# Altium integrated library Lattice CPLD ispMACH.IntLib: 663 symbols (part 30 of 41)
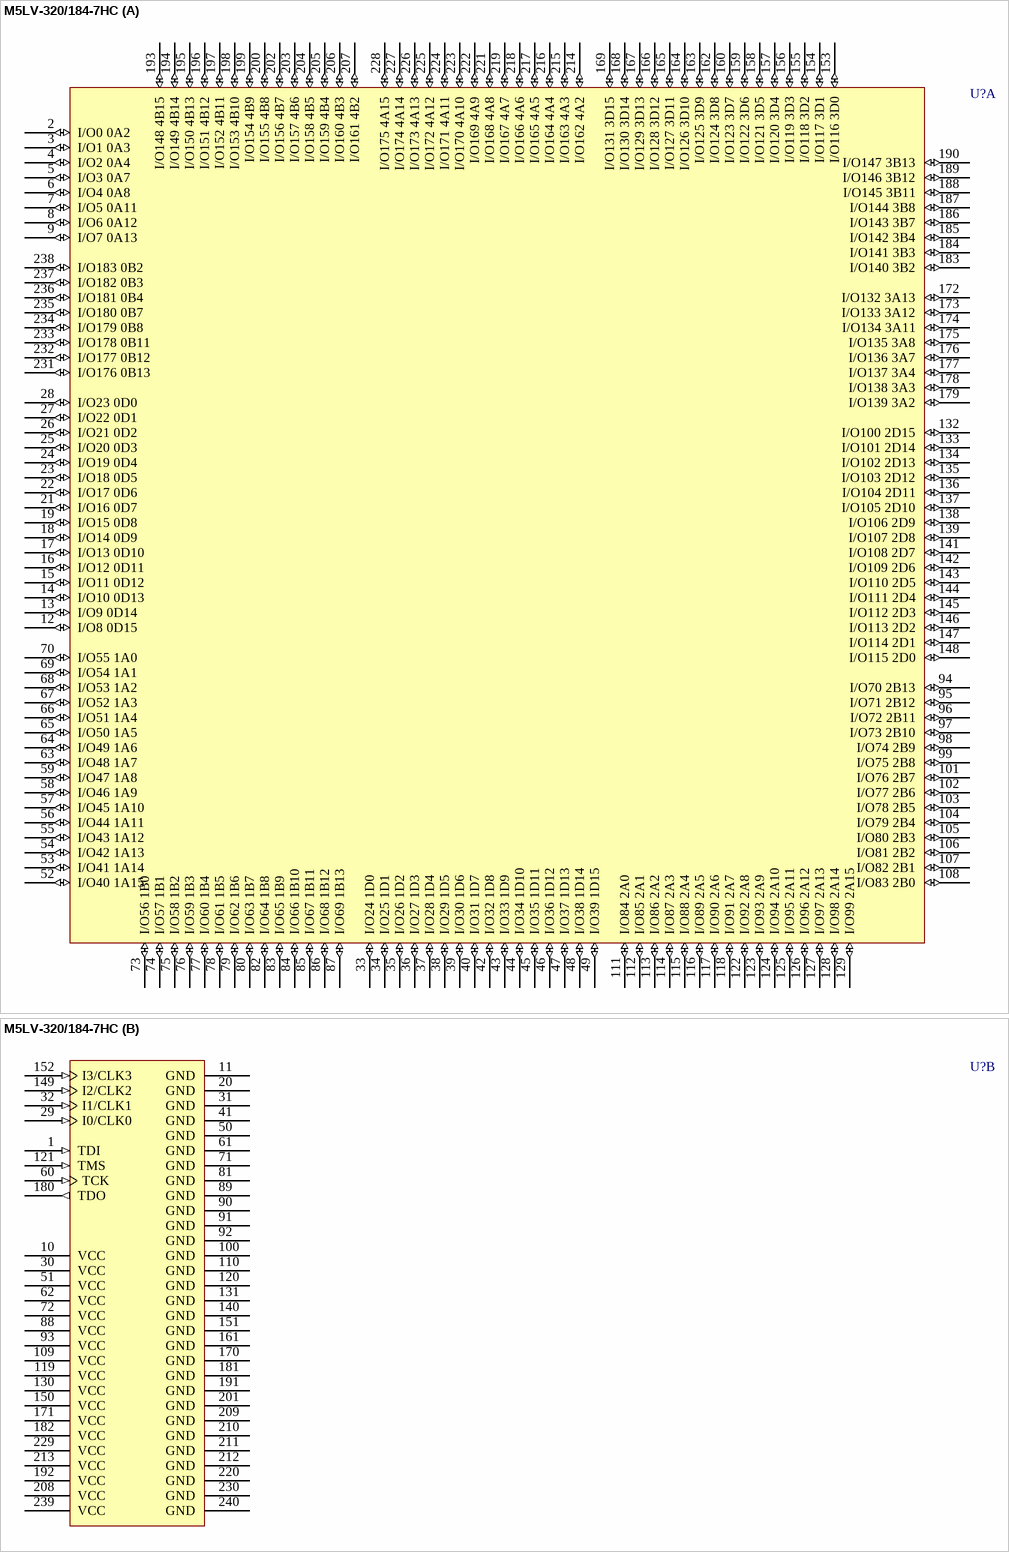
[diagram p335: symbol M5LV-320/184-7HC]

## M5LV-320/184-7HC
designator U?
High-Density and High-I/O Complex PLD
footprint PQFP240_N (Shrink QFP, 240-Leads, Body 32x32mm, Pitch 0.5mm, IPC Medium Density)
footprint PQFP240_L (Shrink QFP, 240-Leads, Body 32x32mm, Pitch 0.5mm, IPC High Density)
footprint PQFP240_M (Shrink QFP, 240-Leads, Body 32x32mm, Pitch 0.5mm, IPC Low Density)
3D model M5LV-PQFP240 (240-Pin Shrink Quad Flat Pack 0.5 mm Pitch)
part A pins: 2 I/O0 0A2 (io), 3 I/O1 0A3 (io), 4 I/O2 0A4 (io), 5 I/O3 0A7 (io), 6 I/O4 0A8 (io), 7 I/O5 0A11 (io), 8 I/O6 0A12 (io), 9 I/O7 0A13 (io), 12 I/O8 0D15 (io), 13 I/O9 0D14 (io), 14 I/O10 0D13 (io), 15 I/O11 0D12 (io), 16 I/O12 0D11 (io), 17 I/O13 0D10 (io), 18 I/O14 0D9 (io), 19 I/O15 0D8 (io), 21 I/O16 0D7 (io), 22 I/O17 0D6 (io), 23 I/O18 0D5 (io), 24 I/O19 0D4 (io), 25 I/O20 0D3 (io), 26 I/O21 0D2 (io), 27 I/O22 0D1 (io), 28 I/O23 0D0 (io), 33 I/O24 1D0 (io), 34 I/O25 1D1 (io), 35 I/O26 1D2 (io), 36 I/O27 1D3 (io), 37 I/O28 1D4 (io), 38 I/O29 1D5 (io), 39 I/O30 1D6 (io), 40 I/O31 1D7 (io), 42 I/O32 1D8 (io), 43 I/O33 1D9 (io), 44 I/O34 1D10 (io), 45 I/O35 1D11 (io), 46 I/O36 1D12 (io), 47 I/O37 1D13 (io), 48 I/O38 1D14 (io), 49 I/O39 1D15 (io), 52 I/O40 1A15 (io), 53 I/O41 1A14 (io), 54 I/O42 1A13 (io), 55 I/O43 1A12 (io), 56 I/O44 1A11 (io), 57 I/O45 1A10 (io), 58 I/O46 1A9 (io), 59 I/O47 1A8 (io), 63 I/O48 1A7 (io), 64 I/O49 1A6 (io), 65 I/O50 1A5 (io), 66 I/O51 1A4 (io), 67 I/O52 1A3 (io), 68 I/O53 1A2 (io), 69 I/O54 1A1 (io), 70 I/O55 1A0 (io), 73 I/O56 1B0 (io), 74 I/O57 1B1 (io), 75 I/O58 1B2 (io), 76 I/O59 1B3 (io), 77 I/O60 1B4 (io), 78 I/O61 1B5 (io), 79 I/O62 1B6 (io), 80 I/O63 1B7 (io), 82 I/O64 1B8 (io), 83 I/O65 1B9 (io), 84 I/O66 1B10 (io), 85 I/O67 1B11 (io), 86 I/O68 1B12 (io), 87 I/O69 1B13 (io), 94 I/O70 2B13 (io), 95 I/O71 2B12 (io), 96 I/O72 2B11 (io), 97 I/O73 2B10 (io), 98 I/O74 2B9 (io), 99 I/O75 2B8 (io), 101 I/O76 2B7 (io), 102 I/O77 2B6 (io), 103 I/O78 2B5 (io), 104 I/O79 2B4 (io), 105 I/O80 2B3 (io), 106 I/O81 2B2 (io), 107 I/O82 2B1 (io), 108 I/O83 2B0 (io), 111 I/O84 2A0 (io), 112 I/O85 2A1 (io), 113 I/O86 2A2 (io), 114 I/O87 2A3 (io), 115 I/O88 2A4 (io), 116 I/O89 2A5 (io), 117 I/O90 2A6 (io), 118 I/O91 2A7 (io), 122 I/O92 2A8 (io), 123 I/O93 2A9 (io), 124 I/O94 2A10 (io), 125 I/O95 2A11 (io), 126 I/O96 2A12 (io), 127 I/O97 2A13 (io), 128 I/O98 2A14 (io), 129 I/O99 2A15 (io), 132 I/O100 2D15 (io), 133 I/O101 2D14 (io), 134 I/O102 2D13 (io), 135 I/O103 2D12 (io), 136 I/O104 2D11 (io), 137 I/O105 2D10 (io), 138 I/O106 2D9 (io), 139 I/O107 2D8 (io), 141 I/O108 2D7 (io), 142 I/O109 2D6 (io), 143 I/O110 2D5 (io), 144 I/O111 2D4 (io), 145 I/O112 2D3 (io), 146 I/O113 2D2 (io), 147 I/O114 2D1 (io), 148 I/O115 2D0 (io), 153 I/O116 3D0 (io), 154 I/O117 3D1 (io), 155 I/O118 3D2 (io), 156 I/O119 3D3 (io), 157 I/O120 3D4 (io), 158 I/O121 3D5 (io), 159 I/O122 3D6 (io), 160 I/O123 3D7 (io), 162 I/O124 3D8 (io), 163 I/O125 3D9 (io), 164 I/O126 3D10 (io), 165 I/O127 3D11 (io), 166 I/O128 3D12 (io), 167 I/O129 3D13 (io), 168 I/O130 3D14 (io), 169 I/O131 3D15 (io), 172 I/O132 3A13 (io), 173 I/O133 3A12 (io), 174 I/O134 3A11 (io), 175 I/O135 3A8 (io), 176 I/O136 3A7 (io), 177 I/O137 3A4 (io), 178 I/O138 3A3 (io), 179 I/O139 3A2 (io), 183 I/O140 3B2 (io), 184 I/O141 3B3 (io), 185 I/O142 3B4 (io), 186 I/O143 3B7 (io), 187 I/O144 3B8 (io), 188 I/O145 3B11 (io), 189 I/O146 3B12 (io), 190 I/O147 3B13 (io), 193 I/O148 4B15 (io), 194 I/O149 4B14 (io), 195 I/O150 4B13 (io), 196 I/O151 4B12 (io), 197 I/O152 4B11 (io), 198 I/O153 4B10 (io), 199 I/O154 4B9 (io), 200 I/O155 4B8 (io), 202 I/O156 4B7 (io), 203 I/O157 4B6 (io), 204 I/O158 4B5 (io), 205 I/O159 4B4 (io), 206 I/O160 4B3 (io), 207 I/O161 4B2 (io), 214 I/O162 4A2 (io), 215 I/O163 4A3 (io), 216 I/O164 4A4 (io), 217 I/O165 4A5 (io), 218 I/O166 4A6 (io), 219 I/O167 4A7 (io), 221 I/O168 4A8 (io), 222 I/O169 4A9 (io), 223 I/O170 4A10 (io), 224 I/O171 4A11 (io), 225 I/O172 4A12 (io), 226 I/O173 4A13 (io), 227 I/O174 4A14 (io), 228 I/O175 4A15 (io), 231 I/O176 0B13 (io), 232 I/O177 0B12 (io), 233 I/O178 0B11 (io), 234 I/O179 0B8 (io), 235 I/O180 0B7 (io), 236 I/O181 0B4 (io), 237 I/O182 0B3 (io), 238 I/O183 0B2 (io)
part B pins: 1 TDI (in), 10 VCC (power), 11 GND (power), 20 GND (power), 29 I0/CLK0 (in), 30 VCC (power), 31 GND (power), 32 I1/CLK1 (in), 41 GND (power), 50 GND (power), 51 VCC (power), 60 TCK (in), 61 GND (power), 62 VCC (power), 71 GND (power), 72 VCC (power), 81 GND (power), 88 VCC (power), 89 GND (power), 90 GND (power), 91 GND (power), 92 GND (power), 93 VCC (power), 100 GND (power), 109 VCC (power), 110 GND (power), 119 VCC (power), 120 GND (power), 121 TMS (in), 130 VCC (power), 131 GND (power), 140 GND (power), 149 I2/CLK2 (in), 150 VCC (power), 151 GND (power), 152 I3/CLK3 (in), 161 GND (power), 170 GND (power), 171 VCC (power), 180 TDO (out), 181 GND (power), 182 VCC (power), 191 GND (power), 192 VCC (power), 201 GND (power), 208 VCC (power), 209 GND (power), 210 GND (power), 211 GND (power), 212 GND (power), 213 VCC (power), 220 GND (power), 229 VCC (power), 230 GND (power), 239 VCC (power), 240 GND (power)

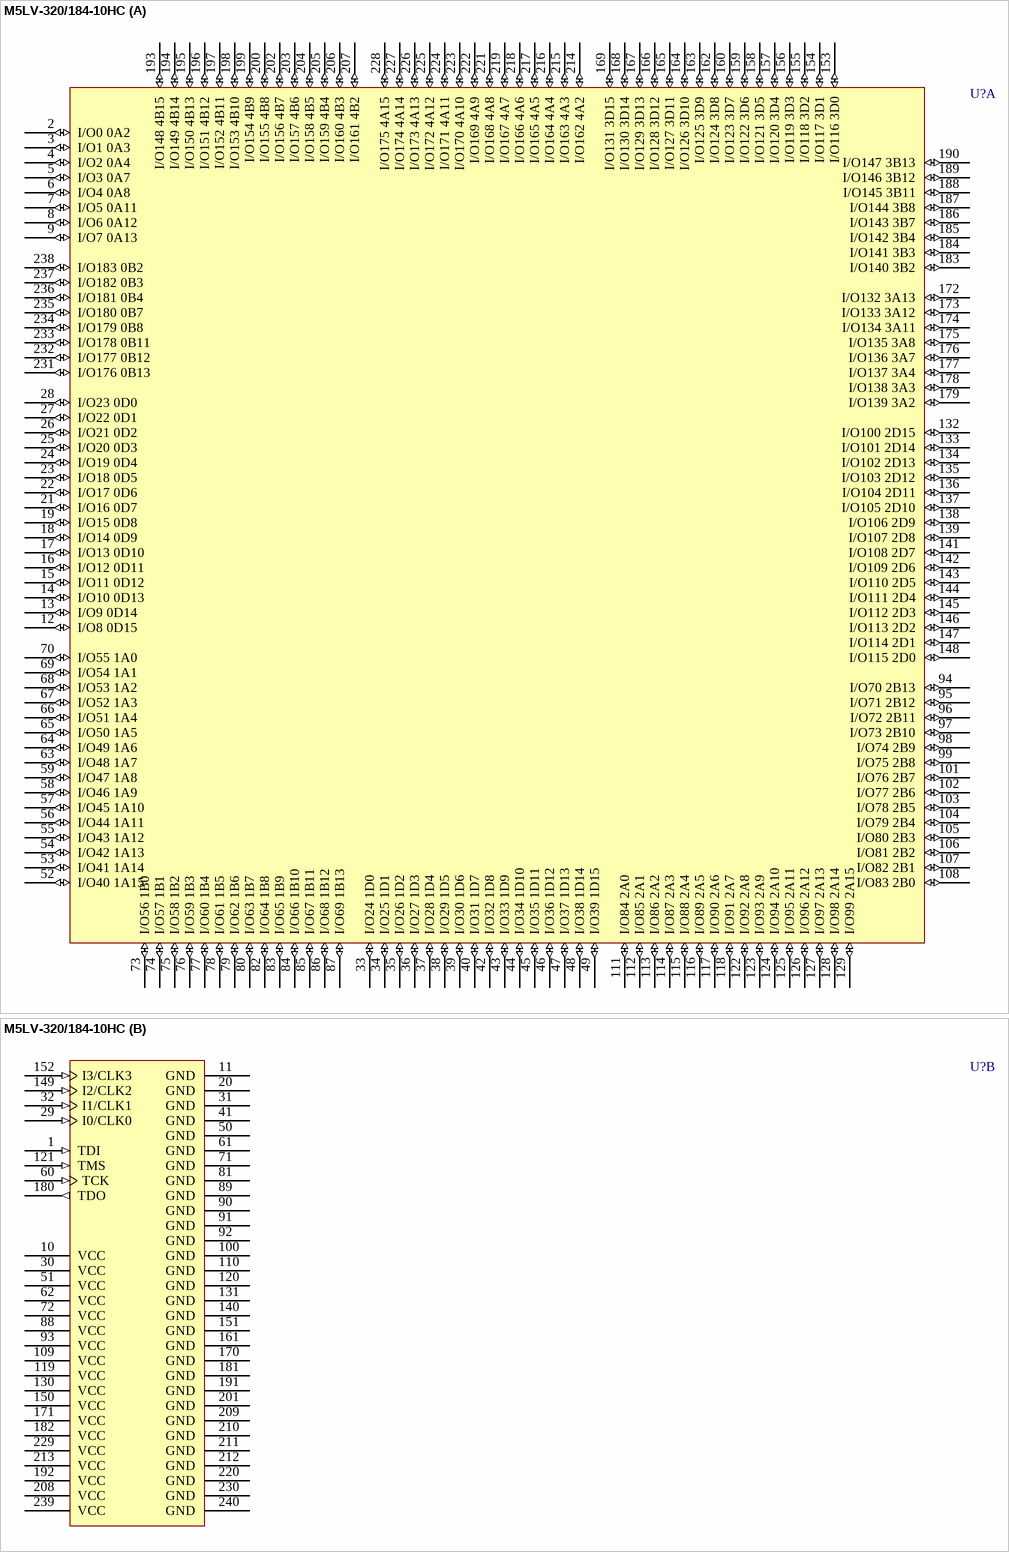
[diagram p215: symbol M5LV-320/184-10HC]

## M5LV-320/184-10HC
designator U?
High-Density and High-I/O Complex PLD
footprint PQFP240_N (Shrink QFP, 240-Leads, Body 32x32mm, Pitch 0.5mm, IPC Medium Density)
footprint PQFP240_L (Shrink QFP, 240-Leads, Body 32x32mm, Pitch 0.5mm, IPC High Density)
footprint PQFP240_M (Shrink QFP, 240-Leads, Body 32x32mm, Pitch 0.5mm, IPC Low Density)
3D model M5LV-PQFP240 (240-Pin Shrink Quad Flat Pack 0.5 mm Pitch)
part A pins: 2 I/O0 0A2 (io), 3 I/O1 0A3 (io), 4 I/O2 0A4 (io), 5 I/O3 0A7 (io), 6 I/O4 0A8 (io), 7 I/O5 0A11 (io), 8 I/O6 0A12 (io), 9 I/O7 0A13 (io), 12 I/O8 0D15 (io), 13 I/O9 0D14 (io), 14 I/O10 0D13 (io), 15 I/O11 0D12 (io), 16 I/O12 0D11 (io), 17 I/O13 0D10 (io), 18 I/O14 0D9 (io), 19 I/O15 0D8 (io), 21 I/O16 0D7 (io), 22 I/O17 0D6 (io), 23 I/O18 0D5 (io), 24 I/O19 0D4 (io), 25 I/O20 0D3 (io), 26 I/O21 0D2 (io), 27 I/O22 0D1 (io), 28 I/O23 0D0 (io), 33 I/O24 1D0 (io), 34 I/O25 1D1 (io), 35 I/O26 1D2 (io), 36 I/O27 1D3 (io), 37 I/O28 1D4 (io), 38 I/O29 1D5 (io), 39 I/O30 1D6 (io), 40 I/O31 1D7 (io), 42 I/O32 1D8 (io), 43 I/O33 1D9 (io), 44 I/O34 1D10 (io), 45 I/O35 1D11 (io), 46 I/O36 1D12 (io), 47 I/O37 1D13 (io), 48 I/O38 1D14 (io), 49 I/O39 1D15 (io), 52 I/O40 1A15 (io), 53 I/O41 1A14 (io), 54 I/O42 1A13 (io), 55 I/O43 1A12 (io), 56 I/O44 1A11 (io), 57 I/O45 1A10 (io), 58 I/O46 1A9 (io), 59 I/O47 1A8 (io), 63 I/O48 1A7 (io), 64 I/O49 1A6 (io), 65 I/O50 1A5 (io), 66 I/O51 1A4 (io), 67 I/O52 1A3 (io), 68 I/O53 1A2 (io), 69 I/O54 1A1 (io), 70 I/O55 1A0 (io), 73 I/O56 1B0 (io), 74 I/O57 1B1 (io), 75 I/O58 1B2 (io), 76 I/O59 1B3 (io), 77 I/O60 1B4 (io), 78 I/O61 1B5 (io), 79 I/O62 1B6 (io), 80 I/O63 1B7 (io), 82 I/O64 1B8 (io), 83 I/O65 1B9 (io), 84 I/O66 1B10 (io), 85 I/O67 1B11 (io), 86 I/O68 1B12 (io), 87 I/O69 1B13 (io), 94 I/O70 2B13 (io), 95 I/O71 2B12 (io), 96 I/O72 2B11 (io), 97 I/O73 2B10 (io), 98 I/O74 2B9 (io), 99 I/O75 2B8 (io), 101 I/O76 2B7 (io), 102 I/O77 2B6 (io), 103 I/O78 2B5 (io), 104 I/O79 2B4 (io), 105 I/O80 2B3 (io), 106 I/O81 2B2 (io), 107 I/O82 2B1 (io), 108 I/O83 2B0 (io), 111 I/O84 2A0 (io), 112 I/O85 2A1 (io), 113 I/O86 2A2 (io), 114 I/O87 2A3 (io), 115 I/O88 2A4 (io), 116 I/O89 2A5 (io), 117 I/O90 2A6 (io), 118 I/O91 2A7 (io), 122 I/O92 2A8 (io), 123 I/O93 2A9 (io), 124 I/O94 2A10 (io), 125 I/O95 2A11 (io), 126 I/O96 2A12 (io), 127 I/O97 2A13 (io), 128 I/O98 2A14 (io), 129 I/O99 2A15 (io), 132 I/O100 2D15 (io), 133 I/O101 2D14 (io), 134 I/O102 2D13 (io), 135 I/O103 2D12 (io), 136 I/O104 2D11 (io), 137 I/O105 2D10 (io), 138 I/O106 2D9 (io), 139 I/O107 2D8 (io), 141 I/O108 2D7 (io), 142 I/O109 2D6 (io), 143 I/O110 2D5 (io), 144 I/O111 2D4 (io), 145 I/O112 2D3 (io), 146 I/O113 2D2 (io), 147 I/O114 2D1 (io), 148 I/O115 2D0 (io), 153 I/O116 3D0 (io), 154 I/O117 3D1 (io), 155 I/O118 3D2 (io), 156 I/O119 3D3 (io), 157 I/O120 3D4 (io), 158 I/O121 3D5 (io), 159 I/O122 3D6 (io), 160 I/O123 3D7 (io), 162 I/O124 3D8 (io), 163 I/O125 3D9 (io), 164 I/O126 3D10 (io), 165 I/O127 3D11 (io), 166 I/O128 3D12 (io), 167 I/O129 3D13 (io), 168 I/O130 3D14 (io), 169 I/O131 3D15 (io), 172 I/O132 3A13 (io), 173 I/O133 3A12 (io), 174 I/O134 3A11 (io), 175 I/O135 3A8 (io), 176 I/O136 3A7 (io), 177 I/O137 3A4 (io), 178 I/O138 3A3 (io), 179 I/O139 3A2 (io), 183 I/O140 3B2 (io), 184 I/O141 3B3 (io), 185 I/O142 3B4 (io), 186 I/O143 3B7 (io), 187 I/O144 3B8 (io), 188 I/O145 3B11 (io), 189 I/O146 3B12 (io), 190 I/O147 3B13 (io), 193 I/O148 4B15 (io), 194 I/O149 4B14 (io), 195 I/O150 4B13 (io), 196 I/O151 4B12 (io), 197 I/O152 4B11 (io), 198 I/O153 4B10 (io), 199 I/O154 4B9 (io), 200 I/O155 4B8 (io), 202 I/O156 4B7 (io), 203 I/O157 4B6 (io), 204 I/O158 4B5 (io), 205 I/O159 4B4 (io), 206 I/O160 4B3 (io), 207 I/O161 4B2 (io), 214 I/O162 4A2 (io), 215 I/O163 4A3 (io), 216 I/O164 4A4 (io), 217 I/O165 4A5 (io), 218 I/O166 4A6 (io), 219 I/O167 4A7 (io), 221 I/O168 4A8 (io), 222 I/O169 4A9 (io), 223 I/O170 4A10 (io), 224 I/O171 4A11 (io), 225 I/O172 4A12 (io), 226 I/O173 4A13 (io), 227 I/O174 4A14 (io), 228 I/O175 4A15 (io), 231 I/O176 0B13 (io), 232 I/O177 0B12 (io), 233 I/O178 0B11 (io), 234 I/O179 0B8 (io), 235 I/O180 0B7 (io), 236 I/O181 0B4 (io), 237 I/O182 0B3 (io), 238 I/O183 0B2 (io)
part B pins: 1 TDI (in), 10 VCC (power), 11 GND (power), 20 GND (power), 29 I0/CLK0 (in), 30 VCC (power), 31 GND (power), 32 I1/CLK1 (in), 41 GND (power), 50 GND (power), 51 VCC (power), 60 TCK (in), 61 GND (power), 62 VCC (power), 71 GND (power), 72 VCC (power), 81 GND (power), 88 VCC (power), 89 GND (power), 90 GND (power), 91 GND (power), 92 GND (power), 93 VCC (power), 100 GND (power), 109 VCC (power), 110 GND (power), 119 VCC (power), 120 GND (power), 121 TMS (in), 130 VCC (power), 131 GND (power), 140 GND (power), 149 I2/CLK2 (in), 150 VCC (power), 151 GND (power), 152 I3/CLK3 (in), 161 GND (power), 170 GND (power), 171 VCC (power), 180 TDO (out), 181 GND (power), 182 VCC (power), 191 GND (power), 192 VCC (power), 201 GND (power), 208 VCC (power), 209 GND (power), 210 GND (power), 211 GND (power), 212 GND (power), 213 VCC (power), 220 GND (power), 229 VCC (power), 230 GND (power), 239 VCC (power), 240 GND (power)

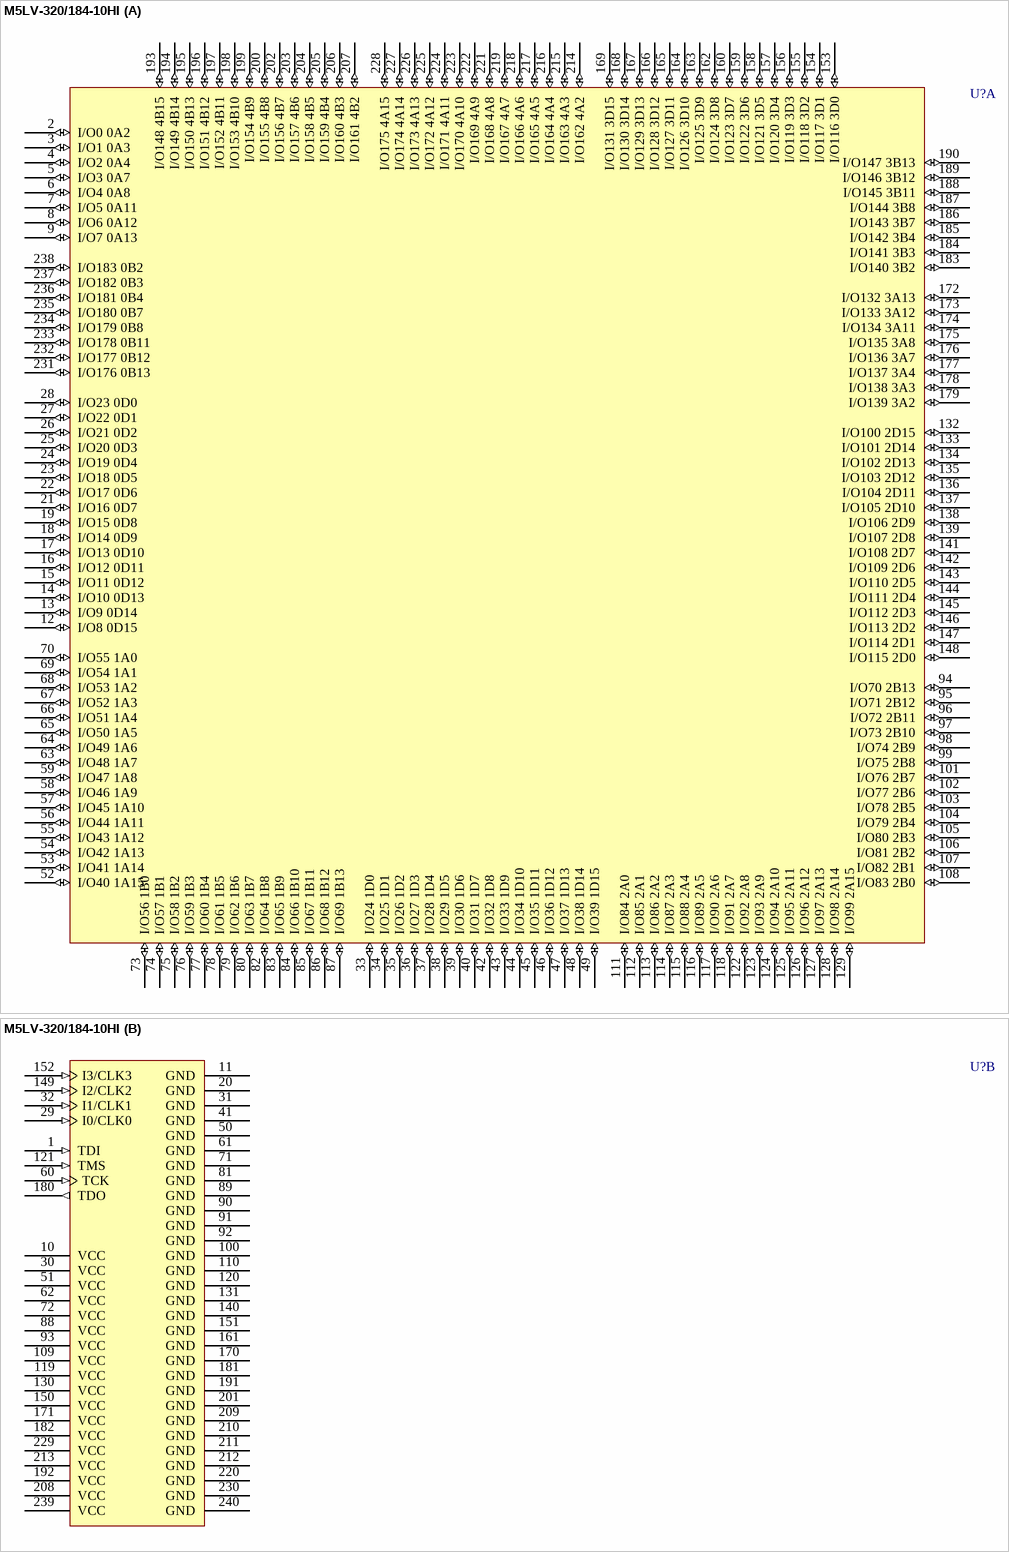
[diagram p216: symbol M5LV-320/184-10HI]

## M5LV-320/184-10HI
designator U?
High-Density and High-I/O Complex PLD
footprint PQFP240_N (Shrink QFP, 240-Leads, Body 32x32mm, Pitch 0.5mm, IPC Medium Density)
footprint PQFP240_L (Shrink QFP, 240-Leads, Body 32x32mm, Pitch 0.5mm, IPC High Density)
footprint PQFP240_M (Shrink QFP, 240-Leads, Body 32x32mm, Pitch 0.5mm, IPC Low Density)
3D model M5LV-PQFP240 (240-Pin Shrink Quad Flat Pack 0.5 mm Pitch)
part A pins: 2 I/O0 0A2 (io), 3 I/O1 0A3 (io), 4 I/O2 0A4 (io), 5 I/O3 0A7 (io), 6 I/O4 0A8 (io), 7 I/O5 0A11 (io), 8 I/O6 0A12 (io), 9 I/O7 0A13 (io), 12 I/O8 0D15 (io), 13 I/O9 0D14 (io), 14 I/O10 0D13 (io), 15 I/O11 0D12 (io), 16 I/O12 0D11 (io), 17 I/O13 0D10 (io), 18 I/O14 0D9 (io), 19 I/O15 0D8 (io), 21 I/O16 0D7 (io), 22 I/O17 0D6 (io), 23 I/O18 0D5 (io), 24 I/O19 0D4 (io), 25 I/O20 0D3 (io), 26 I/O21 0D2 (io), 27 I/O22 0D1 (io), 28 I/O23 0D0 (io), 33 I/O24 1D0 (io), 34 I/O25 1D1 (io), 35 I/O26 1D2 (io), 36 I/O27 1D3 (io), 37 I/O28 1D4 (io), 38 I/O29 1D5 (io), 39 I/O30 1D6 (io), 40 I/O31 1D7 (io), 42 I/O32 1D8 (io), 43 I/O33 1D9 (io), 44 I/O34 1D10 (io), 45 I/O35 1D11 (io), 46 I/O36 1D12 (io), 47 I/O37 1D13 (io), 48 I/O38 1D14 (io), 49 I/O39 1D15 (io), 52 I/O40 1A15 (io), 53 I/O41 1A14 (io), 54 I/O42 1A13 (io), 55 I/O43 1A12 (io), 56 I/O44 1A11 (io), 57 I/O45 1A10 (io), 58 I/O46 1A9 (io), 59 I/O47 1A8 (io), 63 I/O48 1A7 (io), 64 I/O49 1A6 (io), 65 I/O50 1A5 (io), 66 I/O51 1A4 (io), 67 I/O52 1A3 (io), 68 I/O53 1A2 (io), 69 I/O54 1A1 (io), 70 I/O55 1A0 (io), 73 I/O56 1B0 (io), 74 I/O57 1B1 (io), 75 I/O58 1B2 (io), 76 I/O59 1B3 (io), 77 I/O60 1B4 (io), 78 I/O61 1B5 (io), 79 I/O62 1B6 (io), 80 I/O63 1B7 (io), 82 I/O64 1B8 (io), 83 I/O65 1B9 (io), 84 I/O66 1B10 (io), 85 I/O67 1B11 (io), 86 I/O68 1B12 (io), 87 I/O69 1B13 (io), 94 I/O70 2B13 (io), 95 I/O71 2B12 (io), 96 I/O72 2B11 (io), 97 I/O73 2B10 (io), 98 I/O74 2B9 (io), 99 I/O75 2B8 (io), 101 I/O76 2B7 (io), 102 I/O77 2B6 (io), 103 I/O78 2B5 (io), 104 I/O79 2B4 (io), 105 I/O80 2B3 (io), 106 I/O81 2B2 (io), 107 I/O82 2B1 (io), 108 I/O83 2B0 (io), 111 I/O84 2A0 (io), 112 I/O85 2A1 (io), 113 I/O86 2A2 (io), 114 I/O87 2A3 (io), 115 I/O88 2A4 (io), 116 I/O89 2A5 (io), 117 I/O90 2A6 (io), 118 I/O91 2A7 (io), 122 I/O92 2A8 (io), 123 I/O93 2A9 (io), 124 I/O94 2A10 (io), 125 I/O95 2A11 (io), 126 I/O96 2A12 (io), 127 I/O97 2A13 (io), 128 I/O98 2A14 (io), 129 I/O99 2A15 (io), 132 I/O100 2D15 (io), 133 I/O101 2D14 (io), 134 I/O102 2D13 (io), 135 I/O103 2D12 (io), 136 I/O104 2D11 (io), 137 I/O105 2D10 (io), 138 I/O106 2D9 (io), 139 I/O107 2D8 (io), 141 I/O108 2D7 (io), 142 I/O109 2D6 (io), 143 I/O110 2D5 (io), 144 I/O111 2D4 (io), 145 I/O112 2D3 (io), 146 I/O113 2D2 (io), 147 I/O114 2D1 (io), 148 I/O115 2D0 (io), 153 I/O116 3D0 (io), 154 I/O117 3D1 (io), 155 I/O118 3D2 (io), 156 I/O119 3D3 (io), 157 I/O120 3D4 (io), 158 I/O121 3D5 (io), 159 I/O122 3D6 (io), 160 I/O123 3D7 (io), 162 I/O124 3D8 (io), 163 I/O125 3D9 (io), 164 I/O126 3D10 (io), 165 I/O127 3D11 (io), 166 I/O128 3D12 (io), 167 I/O129 3D13 (io), 168 I/O130 3D14 (io), 169 I/O131 3D15 (io), 172 I/O132 3A13 (io), 173 I/O133 3A12 (io), 174 I/O134 3A11 (io), 175 I/O135 3A8 (io), 176 I/O136 3A7 (io), 177 I/O137 3A4 (io), 178 I/O138 3A3 (io), 179 I/O139 3A2 (io), 183 I/O140 3B2 (io), 184 I/O141 3B3 (io), 185 I/O142 3B4 (io), 186 I/O143 3B7 (io), 187 I/O144 3B8 (io), 188 I/O145 3B11 (io), 189 I/O146 3B12 (io), 190 I/O147 3B13 (io), 193 I/O148 4B15 (io), 194 I/O149 4B14 (io), 195 I/O150 4B13 (io), 196 I/O151 4B12 (io), 197 I/O152 4B11 (io), 198 I/O153 4B10 (io), 199 I/O154 4B9 (io), 200 I/O155 4B8 (io), 202 I/O156 4B7 (io), 203 I/O157 4B6 (io), 204 I/O158 4B5 (io), 205 I/O159 4B4 (io), 206 I/O160 4B3 (io), 207 I/O161 4B2 (io), 214 I/O162 4A2 (io), 215 I/O163 4A3 (io), 216 I/O164 4A4 (io), 217 I/O165 4A5 (io), 218 I/O166 4A6 (io), 219 I/O167 4A7 (io), 221 I/O168 4A8 (io), 222 I/O169 4A9 (io), 223 I/O170 4A10 (io), 224 I/O171 4A11 (io), 225 I/O172 4A12 (io), 226 I/O173 4A13 (io), 227 I/O174 4A14 (io), 228 I/O175 4A15 (io), 231 I/O176 0B13 (io), 232 I/O177 0B12 (io), 233 I/O178 0B11 (io), 234 I/O179 0B8 (io), 235 I/O180 0B7 (io), 236 I/O181 0B4 (io), 237 I/O182 0B3 (io), 238 I/O183 0B2 (io)
part B pins: 1 TDI (in), 10 VCC (power), 11 GND (power), 20 GND (power), 29 I0/CLK0 (in), 30 VCC (power), 31 GND (power), 32 I1/CLK1 (in), 41 GND (power), 50 GND (power), 51 VCC (power), 60 TCK (in), 61 GND (power), 62 VCC (power), 71 GND (power), 72 VCC (power), 81 GND (power), 88 VCC (power), 89 GND (power), 90 GND (power), 91 GND (power), 92 GND (power), 93 VCC (power), 100 GND (power), 109 VCC (power), 110 GND (power), 119 VCC (power), 120 GND (power), 121 TMS (in), 130 VCC (power), 131 GND (power), 140 GND (power), 149 I2/CLK2 (in), 150 VCC (power), 151 GND (power), 152 I3/CLK3 (in), 161 GND (power), 170 GND (power), 171 VCC (power), 180 TDO (out), 181 GND (power), 182 VCC (power), 191 GND (power), 192 VCC (power), 201 GND (power), 208 VCC (power), 209 GND (power), 210 GND (power), 211 GND (power), 212 GND (power), 213 VCC (power), 220 GND (power), 229 VCC (power), 230 GND (power), 239 VCC (power), 240 GND (power)

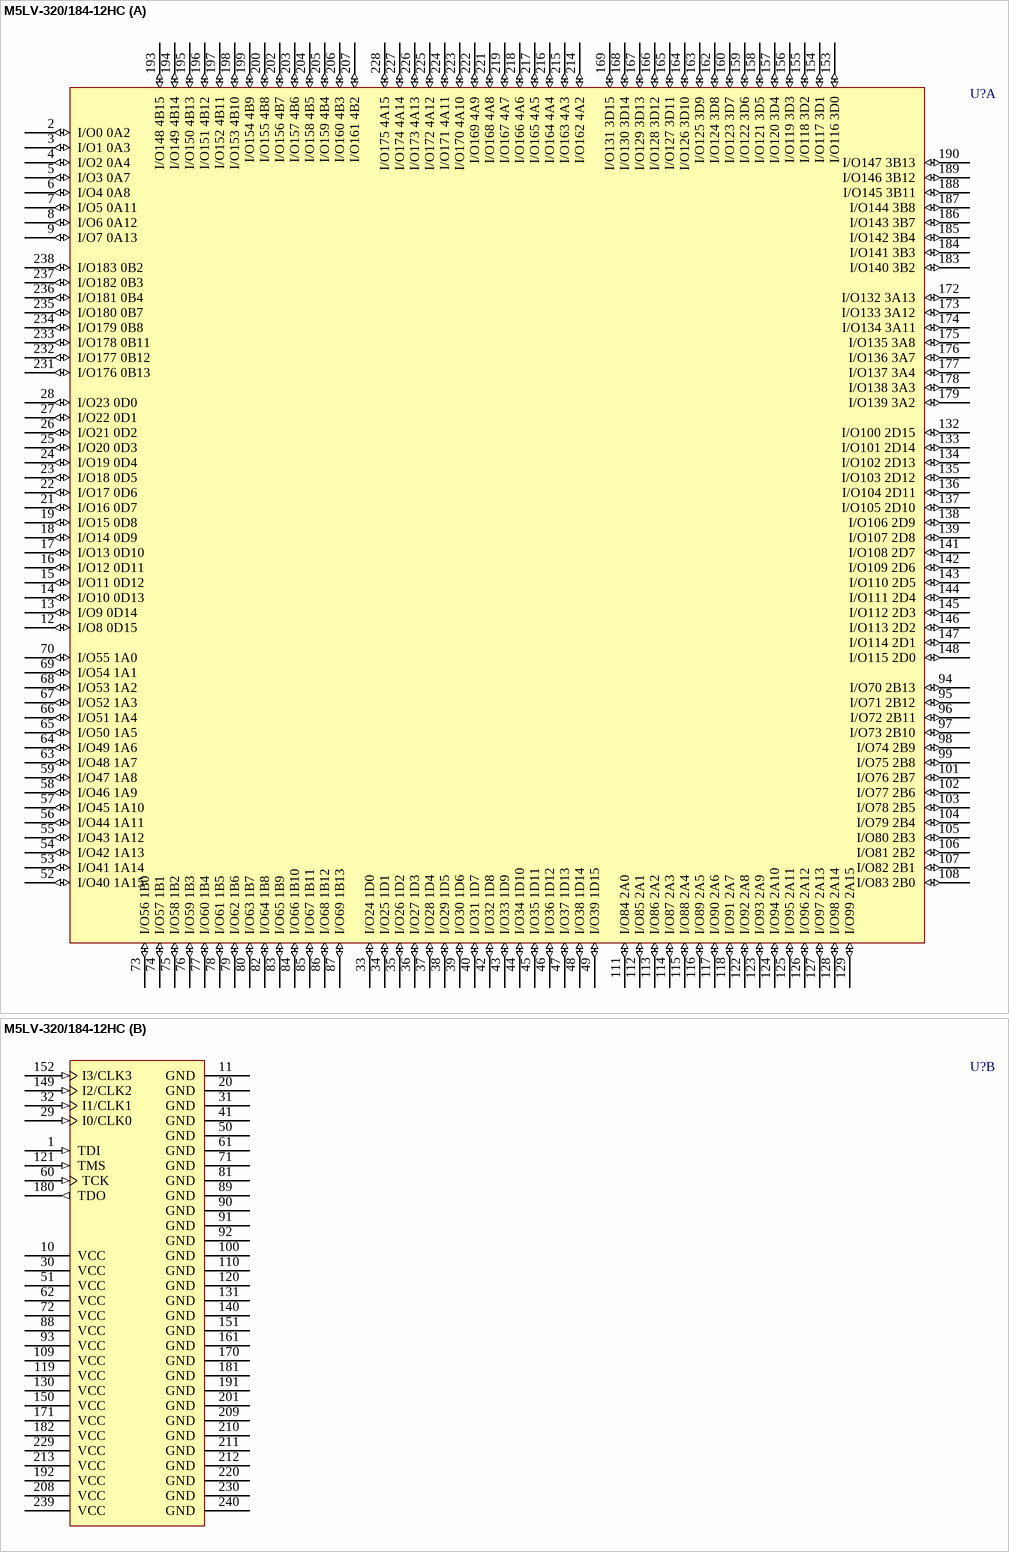
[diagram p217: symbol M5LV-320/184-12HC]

## M5LV-320/184-12HC
designator U?
High-Density and High-I/O Complex PLD
footprint PQFP240_N (Shrink QFP, 240-Leads, Body 32x32mm, Pitch 0.5mm, IPC Medium Density)
footprint PQFP240_L (Shrink QFP, 240-Leads, Body 32x32mm, Pitch 0.5mm, IPC High Density)
footprint PQFP240_M (Shrink QFP, 240-Leads, Body 32x32mm, Pitch 0.5mm, IPC Low Density)
3D model M5LV-PQFP240 (240-Pin Shrink Quad Flat Pack 0.5 mm Pitch)
part A pins: 2 I/O0 0A2 (io), 3 I/O1 0A3 (io), 4 I/O2 0A4 (io), 5 I/O3 0A7 (io), 6 I/O4 0A8 (io), 7 I/O5 0A11 (io), 8 I/O6 0A12 (io), 9 I/O7 0A13 (io), 12 I/O8 0D15 (io), 13 I/O9 0D14 (io), 14 I/O10 0D13 (io), 15 I/O11 0D12 (io), 16 I/O12 0D11 (io), 17 I/O13 0D10 (io), 18 I/O14 0D9 (io), 19 I/O15 0D8 (io), 21 I/O16 0D7 (io), 22 I/O17 0D6 (io), 23 I/O18 0D5 (io), 24 I/O19 0D4 (io), 25 I/O20 0D3 (io), 26 I/O21 0D2 (io), 27 I/O22 0D1 (io), 28 I/O23 0D0 (io), 33 I/O24 1D0 (io), 34 I/O25 1D1 (io), 35 I/O26 1D2 (io), 36 I/O27 1D3 (io), 37 I/O28 1D4 (io), 38 I/O29 1D5 (io), 39 I/O30 1D6 (io), 40 I/O31 1D7 (io), 42 I/O32 1D8 (io), 43 I/O33 1D9 (io), 44 I/O34 1D10 (io), 45 I/O35 1D11 (io), 46 I/O36 1D12 (io), 47 I/O37 1D13 (io), 48 I/O38 1D14 (io), 49 I/O39 1D15 (io), 52 I/O40 1A15 (io), 53 I/O41 1A14 (io), 54 I/O42 1A13 (io), 55 I/O43 1A12 (io), 56 I/O44 1A11 (io), 57 I/O45 1A10 (io), 58 I/O46 1A9 (io), 59 I/O47 1A8 (io), 63 I/O48 1A7 (io), 64 I/O49 1A6 (io), 65 I/O50 1A5 (io), 66 I/O51 1A4 (io), 67 I/O52 1A3 (io), 68 I/O53 1A2 (io), 69 I/O54 1A1 (io), 70 I/O55 1A0 (io), 73 I/O56 1B0 (io), 74 I/O57 1B1 (io), 75 I/O58 1B2 (io), 76 I/O59 1B3 (io), 77 I/O60 1B4 (io), 78 I/O61 1B5 (io), 79 I/O62 1B6 (io), 80 I/O63 1B7 (io), 82 I/O64 1B8 (io), 83 I/O65 1B9 (io), 84 I/O66 1B10 (io), 85 I/O67 1B11 (io), 86 I/O68 1B12 (io), 87 I/O69 1B13 (io), 94 I/O70 2B13 (io), 95 I/O71 2B12 (io), 96 I/O72 2B11 (io), 97 I/O73 2B10 (io), 98 I/O74 2B9 (io), 99 I/O75 2B8 (io), 101 I/O76 2B7 (io), 102 I/O77 2B6 (io), 103 I/O78 2B5 (io), 104 I/O79 2B4 (io), 105 I/O80 2B3 (io), 106 I/O81 2B2 (io), 107 I/O82 2B1 (io), 108 I/O83 2B0 (io), 111 I/O84 2A0 (io), 112 I/O85 2A1 (io), 113 I/O86 2A2 (io), 114 I/O87 2A3 (io), 115 I/O88 2A4 (io), 116 I/O89 2A5 (io), 117 I/O90 2A6 (io), 118 I/O91 2A7 (io), 122 I/O92 2A8 (io), 123 I/O93 2A9 (io), 124 I/O94 2A10 (io), 125 I/O95 2A11 (io), 126 I/O96 2A12 (io), 127 I/O97 2A13 (io), 128 I/O98 2A14 (io), 129 I/O99 2A15 (io), 132 I/O100 2D15 (io), 133 I/O101 2D14 (io), 134 I/O102 2D13 (io), 135 I/O103 2D12 (io), 136 I/O104 2D11 (io), 137 I/O105 2D10 (io), 138 I/O106 2D9 (io), 139 I/O107 2D8 (io), 141 I/O108 2D7 (io), 142 I/O109 2D6 (io), 143 I/O110 2D5 (io), 144 I/O111 2D4 (io), 145 I/O112 2D3 (io), 146 I/O113 2D2 (io), 147 I/O114 2D1 (io), 148 I/O115 2D0 (io), 153 I/O116 3D0 (io), 154 I/O117 3D1 (io), 155 I/O118 3D2 (io), 156 I/O119 3D3 (io), 157 I/O120 3D4 (io), 158 I/O121 3D5 (io), 159 I/O122 3D6 (io), 160 I/O123 3D7 (io), 162 I/O124 3D8 (io), 163 I/O125 3D9 (io), 164 I/O126 3D10 (io), 165 I/O127 3D11 (io), 166 I/O128 3D12 (io), 167 I/O129 3D13 (io), 168 I/O130 3D14 (io), 169 I/O131 3D15 (io), 172 I/O132 3A13 (io), 173 I/O133 3A12 (io), 174 I/O134 3A11 (io), 175 I/O135 3A8 (io), 176 I/O136 3A7 (io), 177 I/O137 3A4 (io), 178 I/O138 3A3 (io), 179 I/O139 3A2 (io), 183 I/O140 3B2 (io), 184 I/O141 3B3 (io), 185 I/O142 3B4 (io), 186 I/O143 3B7 (io), 187 I/O144 3B8 (io), 188 I/O145 3B11 (io), 189 I/O146 3B12 (io), 190 I/O147 3B13 (io), 193 I/O148 4B15 (io), 194 I/O149 4B14 (io), 195 I/O150 4B13 (io), 196 I/O151 4B12 (io), 197 I/O152 4B11 (io), 198 I/O153 4B10 (io), 199 I/O154 4B9 (io), 200 I/O155 4B8 (io), 202 I/O156 4B7 (io), 203 I/O157 4B6 (io), 204 I/O158 4B5 (io), 205 I/O159 4B4 (io), 206 I/O160 4B3 (io), 207 I/O161 4B2 (io), 214 I/O162 4A2 (io), 215 I/O163 4A3 (io), 216 I/O164 4A4 (io), 217 I/O165 4A5 (io), 218 I/O166 4A6 (io), 219 I/O167 4A7 (io), 221 I/O168 4A8 (io), 222 I/O169 4A9 (io), 223 I/O170 4A10 (io), 224 I/O171 4A11 (io), 225 I/O172 4A12 (io), 226 I/O173 4A13 (io), 227 I/O174 4A14 (io), 228 I/O175 4A15 (io), 231 I/O176 0B13 (io), 232 I/O177 0B12 (io), 233 I/O178 0B11 (io), 234 I/O179 0B8 (io), 235 I/O180 0B7 (io), 236 I/O181 0B4 (io), 237 I/O182 0B3 (io), 238 I/O183 0B2 (io)
part B pins: 1 TDI (in), 10 VCC (power), 11 GND (power), 20 GND (power), 29 I0/CLK0 (in), 30 VCC (power), 31 GND (power), 32 I1/CLK1 (in), 41 GND (power), 50 GND (power), 51 VCC (power), 60 TCK (in), 61 GND (power), 62 VCC (power), 71 GND (power), 72 VCC (power), 81 GND (power), 88 VCC (power), 89 GND (power), 90 GND (power), 91 GND (power), 92 GND (power), 93 VCC (power), 100 GND (power), 109 VCC (power), 110 GND (power), 119 VCC (power), 120 GND (power), 121 TMS (in), 130 VCC (power), 131 GND (power), 140 GND (power), 149 I2/CLK2 (in), 150 VCC (power), 151 GND (power), 152 I3/CLK3 (in), 161 GND (power), 170 GND (power), 171 VCC (power), 180 TDO (out), 181 GND (power), 182 VCC (power), 191 GND (power), 192 VCC (power), 201 GND (power), 208 VCC (power), 209 GND (power), 210 GND (power), 211 GND (power), 212 GND (power), 213 VCC (power), 220 GND (power), 229 VCC (power), 230 GND (power), 239 VCC (power), 240 GND (power)

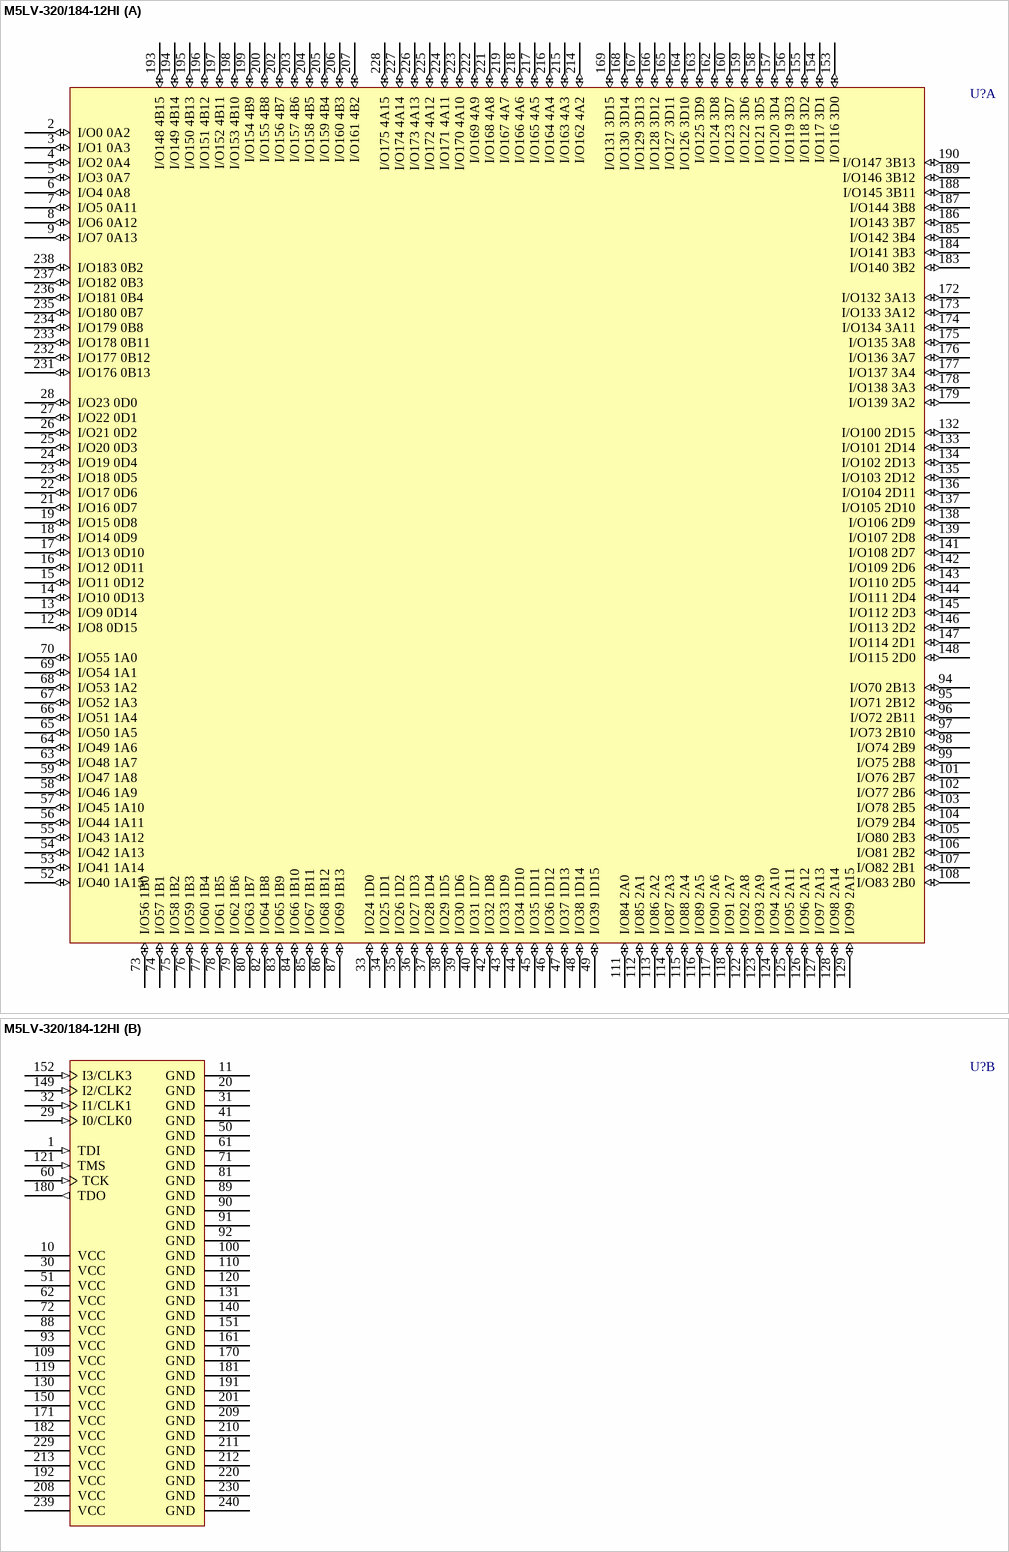
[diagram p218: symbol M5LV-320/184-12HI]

## M5LV-320/184-12HI
designator U?
High-Density and High-I/O Complex PLD
footprint PQFP240_N (Shrink QFP, 240-Leads, Body 32x32mm, Pitch 0.5mm, IPC Medium Density)
footprint PQFP240_L (Shrink QFP, 240-Leads, Body 32x32mm, Pitch 0.5mm, IPC High Density)
footprint PQFP240_M (Shrink QFP, 240-Leads, Body 32x32mm, Pitch 0.5mm, IPC Low Density)
3D model M5LV-PQFP240 (240-Pin Shrink Quad Flat Pack 0.5 mm Pitch)
part A pins: 2 I/O0 0A2 (io), 3 I/O1 0A3 (io), 4 I/O2 0A4 (io), 5 I/O3 0A7 (io), 6 I/O4 0A8 (io), 7 I/O5 0A11 (io), 8 I/O6 0A12 (io), 9 I/O7 0A13 (io), 12 I/O8 0D15 (io), 13 I/O9 0D14 (io), 14 I/O10 0D13 (io), 15 I/O11 0D12 (io), 16 I/O12 0D11 (io), 17 I/O13 0D10 (io), 18 I/O14 0D9 (io), 19 I/O15 0D8 (io), 21 I/O16 0D7 (io), 22 I/O17 0D6 (io), 23 I/O18 0D5 (io), 24 I/O19 0D4 (io), 25 I/O20 0D3 (io), 26 I/O21 0D2 (io), 27 I/O22 0D1 (io), 28 I/O23 0D0 (io), 33 I/O24 1D0 (io), 34 I/O25 1D1 (io), 35 I/O26 1D2 (io), 36 I/O27 1D3 (io), 37 I/O28 1D4 (io), 38 I/O29 1D5 (io), 39 I/O30 1D6 (io), 40 I/O31 1D7 (io), 42 I/O32 1D8 (io), 43 I/O33 1D9 (io), 44 I/O34 1D10 (io), 45 I/O35 1D11 (io), 46 I/O36 1D12 (io), 47 I/O37 1D13 (io), 48 I/O38 1D14 (io), 49 I/O39 1D15 (io), 52 I/O40 1A15 (io), 53 I/O41 1A14 (io), 54 I/O42 1A13 (io), 55 I/O43 1A12 (io), 56 I/O44 1A11 (io), 57 I/O45 1A10 (io), 58 I/O46 1A9 (io), 59 I/O47 1A8 (io), 63 I/O48 1A7 (io), 64 I/O49 1A6 (io), 65 I/O50 1A5 (io), 66 I/O51 1A4 (io), 67 I/O52 1A3 (io), 68 I/O53 1A2 (io), 69 I/O54 1A1 (io), 70 I/O55 1A0 (io), 73 I/O56 1B0 (io), 74 I/O57 1B1 (io), 75 I/O58 1B2 (io), 76 I/O59 1B3 (io), 77 I/O60 1B4 (io), 78 I/O61 1B5 (io), 79 I/O62 1B6 (io), 80 I/O63 1B7 (io), 82 I/O64 1B8 (io), 83 I/O65 1B9 (io), 84 I/O66 1B10 (io), 85 I/O67 1B11 (io), 86 I/O68 1B12 (io), 87 I/O69 1B13 (io), 94 I/O70 2B13 (io), 95 I/O71 2B12 (io), 96 I/O72 2B11 (io), 97 I/O73 2B10 (io), 98 I/O74 2B9 (io), 99 I/O75 2B8 (io), 101 I/O76 2B7 (io), 102 I/O77 2B6 (io), 103 I/O78 2B5 (io), 104 I/O79 2B4 (io), 105 I/O80 2B3 (io), 106 I/O81 2B2 (io), 107 I/O82 2B1 (io), 108 I/O83 2B0 (io), 111 I/O84 2A0 (io), 112 I/O85 2A1 (io), 113 I/O86 2A2 (io), 114 I/O87 2A3 (io), 115 I/O88 2A4 (io), 116 I/O89 2A5 (io), 117 I/O90 2A6 (io), 118 I/O91 2A7 (io), 122 I/O92 2A8 (io), 123 I/O93 2A9 (io), 124 I/O94 2A10 (io), 125 I/O95 2A11 (io), 126 I/O96 2A12 (io), 127 I/O97 2A13 (io), 128 I/O98 2A14 (io), 129 I/O99 2A15 (io), 132 I/O100 2D15 (io), 133 I/O101 2D14 (io), 134 I/O102 2D13 (io), 135 I/O103 2D12 (io), 136 I/O104 2D11 (io), 137 I/O105 2D10 (io), 138 I/O106 2D9 (io), 139 I/O107 2D8 (io), 141 I/O108 2D7 (io), 142 I/O109 2D6 (io), 143 I/O110 2D5 (io), 144 I/O111 2D4 (io), 145 I/O112 2D3 (io), 146 I/O113 2D2 (io), 147 I/O114 2D1 (io), 148 I/O115 2D0 (io), 153 I/O116 3D0 (io), 154 I/O117 3D1 (io), 155 I/O118 3D2 (io), 156 I/O119 3D3 (io), 157 I/O120 3D4 (io), 158 I/O121 3D5 (io), 159 I/O122 3D6 (io), 160 I/O123 3D7 (io), 162 I/O124 3D8 (io), 163 I/O125 3D9 (io), 164 I/O126 3D10 (io), 165 I/O127 3D11 (io), 166 I/O128 3D12 (io), 167 I/O129 3D13 (io), 168 I/O130 3D14 (io), 169 I/O131 3D15 (io), 172 I/O132 3A13 (io), 173 I/O133 3A12 (io), 174 I/O134 3A11 (io), 175 I/O135 3A8 (io), 176 I/O136 3A7 (io), 177 I/O137 3A4 (io), 178 I/O138 3A3 (io), 179 I/O139 3A2 (io), 183 I/O140 3B2 (io), 184 I/O141 3B3 (io), 185 I/O142 3B4 (io), 186 I/O143 3B7 (io), 187 I/O144 3B8 (io), 188 I/O145 3B11 (io), 189 I/O146 3B12 (io), 190 I/O147 3B13 (io), 193 I/O148 4B15 (io), 194 I/O149 4B14 (io), 195 I/O150 4B13 (io), 196 I/O151 4B12 (io), 197 I/O152 4B11 (io), 198 I/O153 4B10 (io), 199 I/O154 4B9 (io), 200 I/O155 4B8 (io), 202 I/O156 4B7 (io), 203 I/O157 4B6 (io), 204 I/O158 4B5 (io), 205 I/O159 4B4 (io), 206 I/O160 4B3 (io), 207 I/O161 4B2 (io), 214 I/O162 4A2 (io), 215 I/O163 4A3 (io), 216 I/O164 4A4 (io), 217 I/O165 4A5 (io), 218 I/O166 4A6 (io), 219 I/O167 4A7 (io), 221 I/O168 4A8 (io), 222 I/O169 4A9 (io), 223 I/O170 4A10 (io), 224 I/O171 4A11 (io), 225 I/O172 4A12 (io), 226 I/O173 4A13 (io), 227 I/O174 4A14 (io), 228 I/O175 4A15 (io), 231 I/O176 0B13 (io), 232 I/O177 0B12 (io), 233 I/O178 0B11 (io), 234 I/O179 0B8 (io), 235 I/O180 0B7 (io), 236 I/O181 0B4 (io), 237 I/O182 0B3 (io), 238 I/O183 0B2 (io)
part B pins: 1 TDI (in), 10 VCC (power), 11 GND (power), 20 GND (power), 29 I0/CLK0 (in), 30 VCC (power), 31 GND (power), 32 I1/CLK1 (in), 41 GND (power), 50 GND (power), 51 VCC (power), 60 TCK (in), 61 GND (power), 62 VCC (power), 71 GND (power), 72 VCC (power), 81 GND (power), 88 VCC (power), 89 GND (power), 90 GND (power), 91 GND (power), 92 GND (power), 93 VCC (power), 100 GND (power), 109 VCC (power), 110 GND (power), 119 VCC (power), 120 GND (power), 121 TMS (in), 130 VCC (power), 131 GND (power), 140 GND (power), 149 I2/CLK2 (in), 150 VCC (power), 151 GND (power), 152 I3/CLK3 (in), 161 GND (power), 170 GND (power), 171 VCC (power), 180 TDO (out), 181 GND (power), 182 VCC (power), 191 GND (power), 192 VCC (power), 201 GND (power), 208 VCC (power), 209 GND (power), 210 GND (power), 211 GND (power), 212 GND (power), 213 VCC (power), 220 GND (power), 229 VCC (power), 230 GND (power), 239 VCC (power), 240 GND (power)

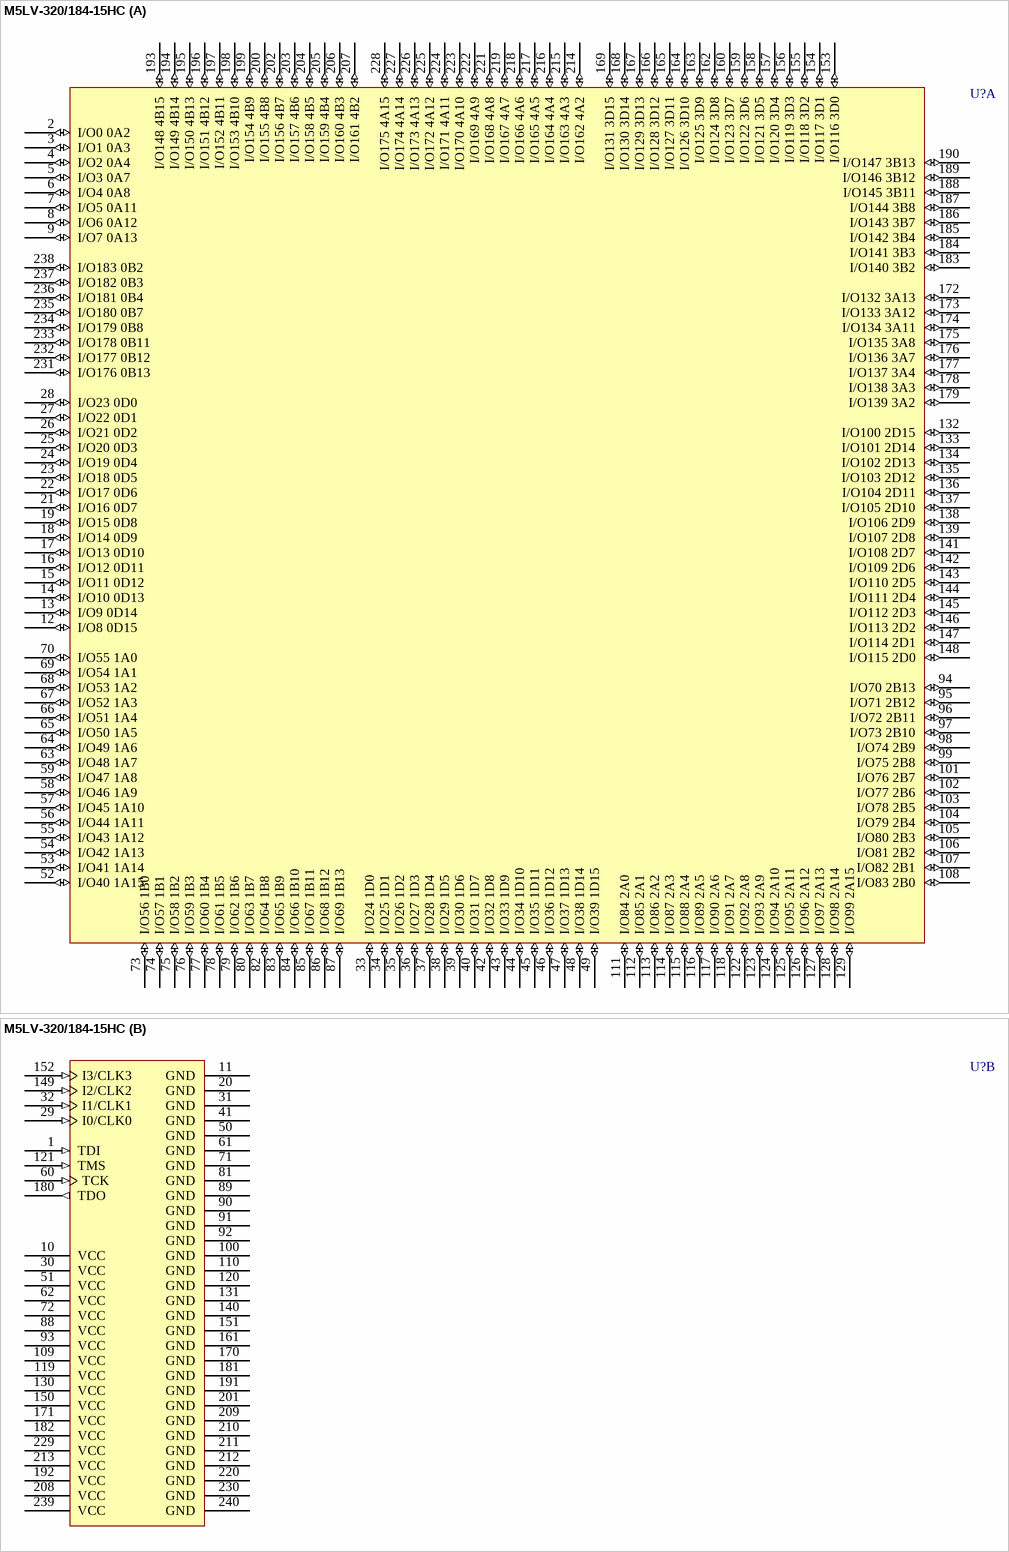
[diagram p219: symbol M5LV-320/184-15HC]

## M5LV-320/184-15HC
designator U?
High-Density and High-I/O Complex PLD
footprint PQFP240_N (Shrink QFP, 240-Leads, Body 32x32mm, Pitch 0.5mm, IPC Medium Density)
footprint PQFP240_L (Shrink QFP, 240-Leads, Body 32x32mm, Pitch 0.5mm, IPC High Density)
footprint PQFP240_M (Shrink QFP, 240-Leads, Body 32x32mm, Pitch 0.5mm, IPC Low Density)
3D model M5LV-PQFP240 (240-Pin Shrink Quad Flat Pack 0.5 mm Pitch)
part A pins: 2 I/O0 0A2 (io), 3 I/O1 0A3 (io), 4 I/O2 0A4 (io), 5 I/O3 0A7 (io), 6 I/O4 0A8 (io), 7 I/O5 0A11 (io), 8 I/O6 0A12 (io), 9 I/O7 0A13 (io), 12 I/O8 0D15 (io), 13 I/O9 0D14 (io), 14 I/O10 0D13 (io), 15 I/O11 0D12 (io), 16 I/O12 0D11 (io), 17 I/O13 0D10 (io), 18 I/O14 0D9 (io), 19 I/O15 0D8 (io), 21 I/O16 0D7 (io), 22 I/O17 0D6 (io), 23 I/O18 0D5 (io), 24 I/O19 0D4 (io), 25 I/O20 0D3 (io), 26 I/O21 0D2 (io), 27 I/O22 0D1 (io), 28 I/O23 0D0 (io), 33 I/O24 1D0 (io), 34 I/O25 1D1 (io), 35 I/O26 1D2 (io), 36 I/O27 1D3 (io), 37 I/O28 1D4 (io), 38 I/O29 1D5 (io), 39 I/O30 1D6 (io), 40 I/O31 1D7 (io), 42 I/O32 1D8 (io), 43 I/O33 1D9 (io), 44 I/O34 1D10 (io), 45 I/O35 1D11 (io), 46 I/O36 1D12 (io), 47 I/O37 1D13 (io), 48 I/O38 1D14 (io), 49 I/O39 1D15 (io), 52 I/O40 1A15 (io), 53 I/O41 1A14 (io), 54 I/O42 1A13 (io), 55 I/O43 1A12 (io), 56 I/O44 1A11 (io), 57 I/O45 1A10 (io), 58 I/O46 1A9 (io), 59 I/O47 1A8 (io), 63 I/O48 1A7 (io), 64 I/O49 1A6 (io), 65 I/O50 1A5 (io), 66 I/O51 1A4 (io), 67 I/O52 1A3 (io), 68 I/O53 1A2 (io), 69 I/O54 1A1 (io), 70 I/O55 1A0 (io), 73 I/O56 1B0 (io), 74 I/O57 1B1 (io), 75 I/O58 1B2 (io), 76 I/O59 1B3 (io), 77 I/O60 1B4 (io), 78 I/O61 1B5 (io), 79 I/O62 1B6 (io), 80 I/O63 1B7 (io), 82 I/O64 1B8 (io), 83 I/O65 1B9 (io), 84 I/O66 1B10 (io), 85 I/O67 1B11 (io), 86 I/O68 1B12 (io), 87 I/O69 1B13 (io), 94 I/O70 2B13 (io), 95 I/O71 2B12 (io), 96 I/O72 2B11 (io), 97 I/O73 2B10 (io), 98 I/O74 2B9 (io), 99 I/O75 2B8 (io), 101 I/O76 2B7 (io), 102 I/O77 2B6 (io), 103 I/O78 2B5 (io), 104 I/O79 2B4 (io), 105 I/O80 2B3 (io), 106 I/O81 2B2 (io), 107 I/O82 2B1 (io), 108 I/O83 2B0 (io), 111 I/O84 2A0 (io), 112 I/O85 2A1 (io), 113 I/O86 2A2 (io), 114 I/O87 2A3 (io), 115 I/O88 2A4 (io), 116 I/O89 2A5 (io), 117 I/O90 2A6 (io), 118 I/O91 2A7 (io), 122 I/O92 2A8 (io), 123 I/O93 2A9 (io), 124 I/O94 2A10 (io), 125 I/O95 2A11 (io), 126 I/O96 2A12 (io), 127 I/O97 2A13 (io), 128 I/O98 2A14 (io), 129 I/O99 2A15 (io), 132 I/O100 2D15 (io), 133 I/O101 2D14 (io), 134 I/O102 2D13 (io), 135 I/O103 2D12 (io), 136 I/O104 2D11 (io), 137 I/O105 2D10 (io), 138 I/O106 2D9 (io), 139 I/O107 2D8 (io), 141 I/O108 2D7 (io), 142 I/O109 2D6 (io), 143 I/O110 2D5 (io), 144 I/O111 2D4 (io), 145 I/O112 2D3 (io), 146 I/O113 2D2 (io), 147 I/O114 2D1 (io), 148 I/O115 2D0 (io), 153 I/O116 3D0 (io), 154 I/O117 3D1 (io), 155 I/O118 3D2 (io), 156 I/O119 3D3 (io), 157 I/O120 3D4 (io), 158 I/O121 3D5 (io), 159 I/O122 3D6 (io), 160 I/O123 3D7 (io), 162 I/O124 3D8 (io), 163 I/O125 3D9 (io), 164 I/O126 3D10 (io), 165 I/O127 3D11 (io), 166 I/O128 3D12 (io), 167 I/O129 3D13 (io), 168 I/O130 3D14 (io), 169 I/O131 3D15 (io), 172 I/O132 3A13 (io), 173 I/O133 3A12 (io), 174 I/O134 3A11 (io), 175 I/O135 3A8 (io), 176 I/O136 3A7 (io), 177 I/O137 3A4 (io), 178 I/O138 3A3 (io), 179 I/O139 3A2 (io), 183 I/O140 3B2 (io), 184 I/O141 3B3 (io), 185 I/O142 3B4 (io), 186 I/O143 3B7 (io), 187 I/O144 3B8 (io), 188 I/O145 3B11 (io), 189 I/O146 3B12 (io), 190 I/O147 3B13 (io), 193 I/O148 4B15 (io), 194 I/O149 4B14 (io), 195 I/O150 4B13 (io), 196 I/O151 4B12 (io), 197 I/O152 4B11 (io), 198 I/O153 4B10 (io), 199 I/O154 4B9 (io), 200 I/O155 4B8 (io), 202 I/O156 4B7 (io), 203 I/O157 4B6 (io), 204 I/O158 4B5 (io), 205 I/O159 4B4 (io), 206 I/O160 4B3 (io), 207 I/O161 4B2 (io), 214 I/O162 4A2 (io), 215 I/O163 4A3 (io), 216 I/O164 4A4 (io), 217 I/O165 4A5 (io), 218 I/O166 4A6 (io), 219 I/O167 4A7 (io), 221 I/O168 4A8 (io), 222 I/O169 4A9 (io), 223 I/O170 4A10 (io), 224 I/O171 4A11 (io), 225 I/O172 4A12 (io), 226 I/O173 4A13 (io), 227 I/O174 4A14 (io), 228 I/O175 4A15 (io), 231 I/O176 0B13 (io), 232 I/O177 0B12 (io), 233 I/O178 0B11 (io), 234 I/O179 0B8 (io), 235 I/O180 0B7 (io), 236 I/O181 0B4 (io), 237 I/O182 0B3 (io), 238 I/O183 0B2 (io)
part B pins: 1 TDI (in), 10 VCC (power), 11 GND (power), 20 GND (power), 29 I0/CLK0 (in), 30 VCC (power), 31 GND (power), 32 I1/CLK1 (in), 41 GND (power), 50 GND (power), 51 VCC (power), 60 TCK (in), 61 GND (power), 62 VCC (power), 71 GND (power), 72 VCC (power), 81 GND (power), 88 VCC (power), 89 GND (power), 90 GND (power), 91 GND (power), 92 GND (power), 93 VCC (power), 100 GND (power), 109 VCC (power), 110 GND (power), 119 VCC (power), 120 GND (power), 121 TMS (in), 130 VCC (power), 131 GND (power), 140 GND (power), 149 I2/CLK2 (in), 150 VCC (power), 151 GND (power), 152 I3/CLK3 (in), 161 GND (power), 170 GND (power), 171 VCC (power), 180 TDO (out), 181 GND (power), 182 VCC (power), 191 GND (power), 192 VCC (power), 201 GND (power), 208 VCC (power), 209 GND (power), 210 GND (power), 211 GND (power), 212 GND (power), 213 VCC (power), 220 GND (power), 229 VCC (power), 230 GND (power), 239 VCC (power), 240 GND (power)

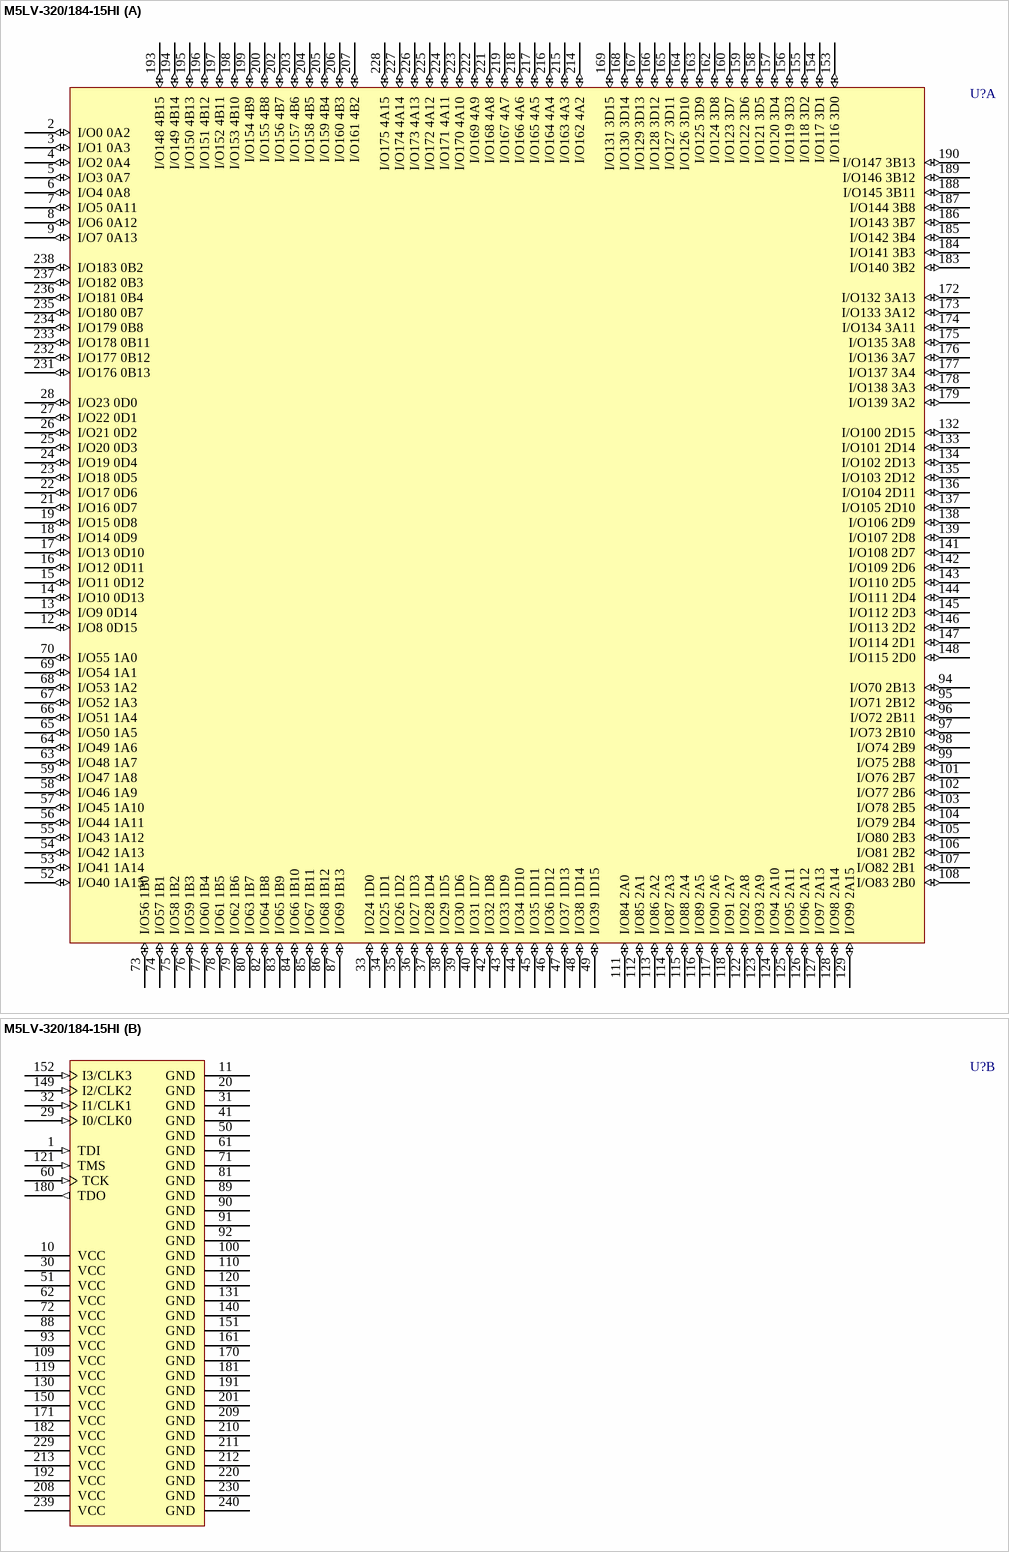
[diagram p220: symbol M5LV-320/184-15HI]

## M5LV-320/184-15HI
designator U?
High-Density and High-I/O Complex PLD
footprint PQFP240_N (Shrink QFP, 240-Leads, Body 32x32mm, Pitch 0.5mm, IPC Medium Density)
footprint PQFP240_L (Shrink QFP, 240-Leads, Body 32x32mm, Pitch 0.5mm, IPC High Density)
footprint PQFP240_M (Shrink QFP, 240-Leads, Body 32x32mm, Pitch 0.5mm, IPC Low Density)
3D model M5LV-PQFP240 (240-Pin Shrink Quad Flat Pack 0.5 mm Pitch)
part A pins: 2 I/O0 0A2 (io), 3 I/O1 0A3 (io), 4 I/O2 0A4 (io), 5 I/O3 0A7 (io), 6 I/O4 0A8 (io), 7 I/O5 0A11 (io), 8 I/O6 0A12 (io), 9 I/O7 0A13 (io), 12 I/O8 0D15 (io), 13 I/O9 0D14 (io), 14 I/O10 0D13 (io), 15 I/O11 0D12 (io), 16 I/O12 0D11 (io), 17 I/O13 0D10 (io), 18 I/O14 0D9 (io), 19 I/O15 0D8 (io), 21 I/O16 0D7 (io), 22 I/O17 0D6 (io), 23 I/O18 0D5 (io), 24 I/O19 0D4 (io), 25 I/O20 0D3 (io), 26 I/O21 0D2 (io), 27 I/O22 0D1 (io), 28 I/O23 0D0 (io), 33 I/O24 1D0 (io), 34 I/O25 1D1 (io), 35 I/O26 1D2 (io), 36 I/O27 1D3 (io), 37 I/O28 1D4 (io), 38 I/O29 1D5 (io), 39 I/O30 1D6 (io), 40 I/O31 1D7 (io), 42 I/O32 1D8 (io), 43 I/O33 1D9 (io), 44 I/O34 1D10 (io), 45 I/O35 1D11 (io), 46 I/O36 1D12 (io), 47 I/O37 1D13 (io), 48 I/O38 1D14 (io), 49 I/O39 1D15 (io), 52 I/O40 1A15 (io), 53 I/O41 1A14 (io), 54 I/O42 1A13 (io), 55 I/O43 1A12 (io), 56 I/O44 1A11 (io), 57 I/O45 1A10 (io), 58 I/O46 1A9 (io), 59 I/O47 1A8 (io), 63 I/O48 1A7 (io), 64 I/O49 1A6 (io), 65 I/O50 1A5 (io), 66 I/O51 1A4 (io), 67 I/O52 1A3 (io), 68 I/O53 1A2 (io), 69 I/O54 1A1 (io), 70 I/O55 1A0 (io), 73 I/O56 1B0 (io), 74 I/O57 1B1 (io), 75 I/O58 1B2 (io), 76 I/O59 1B3 (io), 77 I/O60 1B4 (io), 78 I/O61 1B5 (io), 79 I/O62 1B6 (io), 80 I/O63 1B7 (io), 82 I/O64 1B8 (io), 83 I/O65 1B9 (io), 84 I/O66 1B10 (io), 85 I/O67 1B11 (io), 86 I/O68 1B12 (io), 87 I/O69 1B13 (io), 94 I/O70 2B13 (io), 95 I/O71 2B12 (io), 96 I/O72 2B11 (io), 97 I/O73 2B10 (io), 98 I/O74 2B9 (io), 99 I/O75 2B8 (io), 101 I/O76 2B7 (io), 102 I/O77 2B6 (io), 103 I/O78 2B5 (io), 104 I/O79 2B4 (io), 105 I/O80 2B3 (io), 106 I/O81 2B2 (io), 107 I/O82 2B1 (io), 108 I/O83 2B0 (io), 111 I/O84 2A0 (io), 112 I/O85 2A1 (io), 113 I/O86 2A2 (io), 114 I/O87 2A3 (io), 115 I/O88 2A4 (io), 116 I/O89 2A5 (io), 117 I/O90 2A6 (io), 118 I/O91 2A7 (io), 122 I/O92 2A8 (io), 123 I/O93 2A9 (io), 124 I/O94 2A10 (io), 125 I/O95 2A11 (io), 126 I/O96 2A12 (io), 127 I/O97 2A13 (io), 128 I/O98 2A14 (io), 129 I/O99 2A15 (io), 132 I/O100 2D15 (io), 133 I/O101 2D14 (io), 134 I/O102 2D13 (io), 135 I/O103 2D12 (io), 136 I/O104 2D11 (io), 137 I/O105 2D10 (io), 138 I/O106 2D9 (io), 139 I/O107 2D8 (io), 141 I/O108 2D7 (io), 142 I/O109 2D6 (io), 143 I/O110 2D5 (io), 144 I/O111 2D4 (io), 145 I/O112 2D3 (io), 146 I/O113 2D2 (io), 147 I/O114 2D1 (io), 148 I/O115 2D0 (io), 153 I/O116 3D0 (io), 154 I/O117 3D1 (io), 155 I/O118 3D2 (io), 156 I/O119 3D3 (io), 157 I/O120 3D4 (io), 158 I/O121 3D5 (io), 159 I/O122 3D6 (io), 160 I/O123 3D7 (io), 162 I/O124 3D8 (io), 163 I/O125 3D9 (io), 164 I/O126 3D10 (io), 165 I/O127 3D11 (io), 166 I/O128 3D12 (io), 167 I/O129 3D13 (io), 168 I/O130 3D14 (io), 169 I/O131 3D15 (io), 172 I/O132 3A13 (io), 173 I/O133 3A12 (io), 174 I/O134 3A11 (io), 175 I/O135 3A8 (io), 176 I/O136 3A7 (io), 177 I/O137 3A4 (io), 178 I/O138 3A3 (io), 179 I/O139 3A2 (io), 183 I/O140 3B2 (io), 184 I/O141 3B3 (io), 185 I/O142 3B4 (io), 186 I/O143 3B7 (io), 187 I/O144 3B8 (io), 188 I/O145 3B11 (io), 189 I/O146 3B12 (io), 190 I/O147 3B13 (io), 193 I/O148 4B15 (io), 194 I/O149 4B14 (io), 195 I/O150 4B13 (io), 196 I/O151 4B12 (io), 197 I/O152 4B11 (io), 198 I/O153 4B10 (io), 199 I/O154 4B9 (io), 200 I/O155 4B8 (io), 202 I/O156 4B7 (io), 203 I/O157 4B6 (io), 204 I/O158 4B5 (io), 205 I/O159 4B4 (io), 206 I/O160 4B3 (io), 207 I/O161 4B2 (io), 214 I/O162 4A2 (io), 215 I/O163 4A3 (io), 216 I/O164 4A4 (io), 217 I/O165 4A5 (io), 218 I/O166 4A6 (io), 219 I/O167 4A7 (io), 221 I/O168 4A8 (io), 222 I/O169 4A9 (io), 223 I/O170 4A10 (io), 224 I/O171 4A11 (io), 225 I/O172 4A12 (io), 226 I/O173 4A13 (io), 227 I/O174 4A14 (io), 228 I/O175 4A15 (io), 231 I/O176 0B13 (io), 232 I/O177 0B12 (io), 233 I/O178 0B11 (io), 234 I/O179 0B8 (io), 235 I/O180 0B7 (io), 236 I/O181 0B4 (io), 237 I/O182 0B3 (io), 238 I/O183 0B2 (io)
part B pins: 1 TDI (in), 10 VCC (power), 11 GND (power), 20 GND (power), 29 I0/CLK0 (in), 30 VCC (power), 31 GND (power), 32 I1/CLK1 (in), 41 GND (power), 50 GND (power), 51 VCC (power), 60 TCK (in), 61 GND (power), 62 VCC (power), 71 GND (power), 72 VCC (power), 81 GND (power), 88 VCC (power), 89 GND (power), 90 GND (power), 91 GND (power), 92 GND (power), 93 VCC (power), 100 GND (power), 109 VCC (power), 110 GND (power), 119 VCC (power), 120 GND (power), 121 TMS (in), 130 VCC (power), 131 GND (power), 140 GND (power), 149 I2/CLK2 (in), 150 VCC (power), 151 GND (power), 152 I3/CLK3 (in), 161 GND (power), 170 GND (power), 171 VCC (power), 180 TDO (out), 181 GND (power), 182 VCC (power), 191 GND (power), 192 VCC (power), 201 GND (power), 208 VCC (power), 209 GND (power), 210 GND (power), 211 GND (power), 212 GND (power), 213 VCC (power), 220 GND (power), 229 VCC (power), 230 GND (power), 239 VCC (power), 240 GND (power)

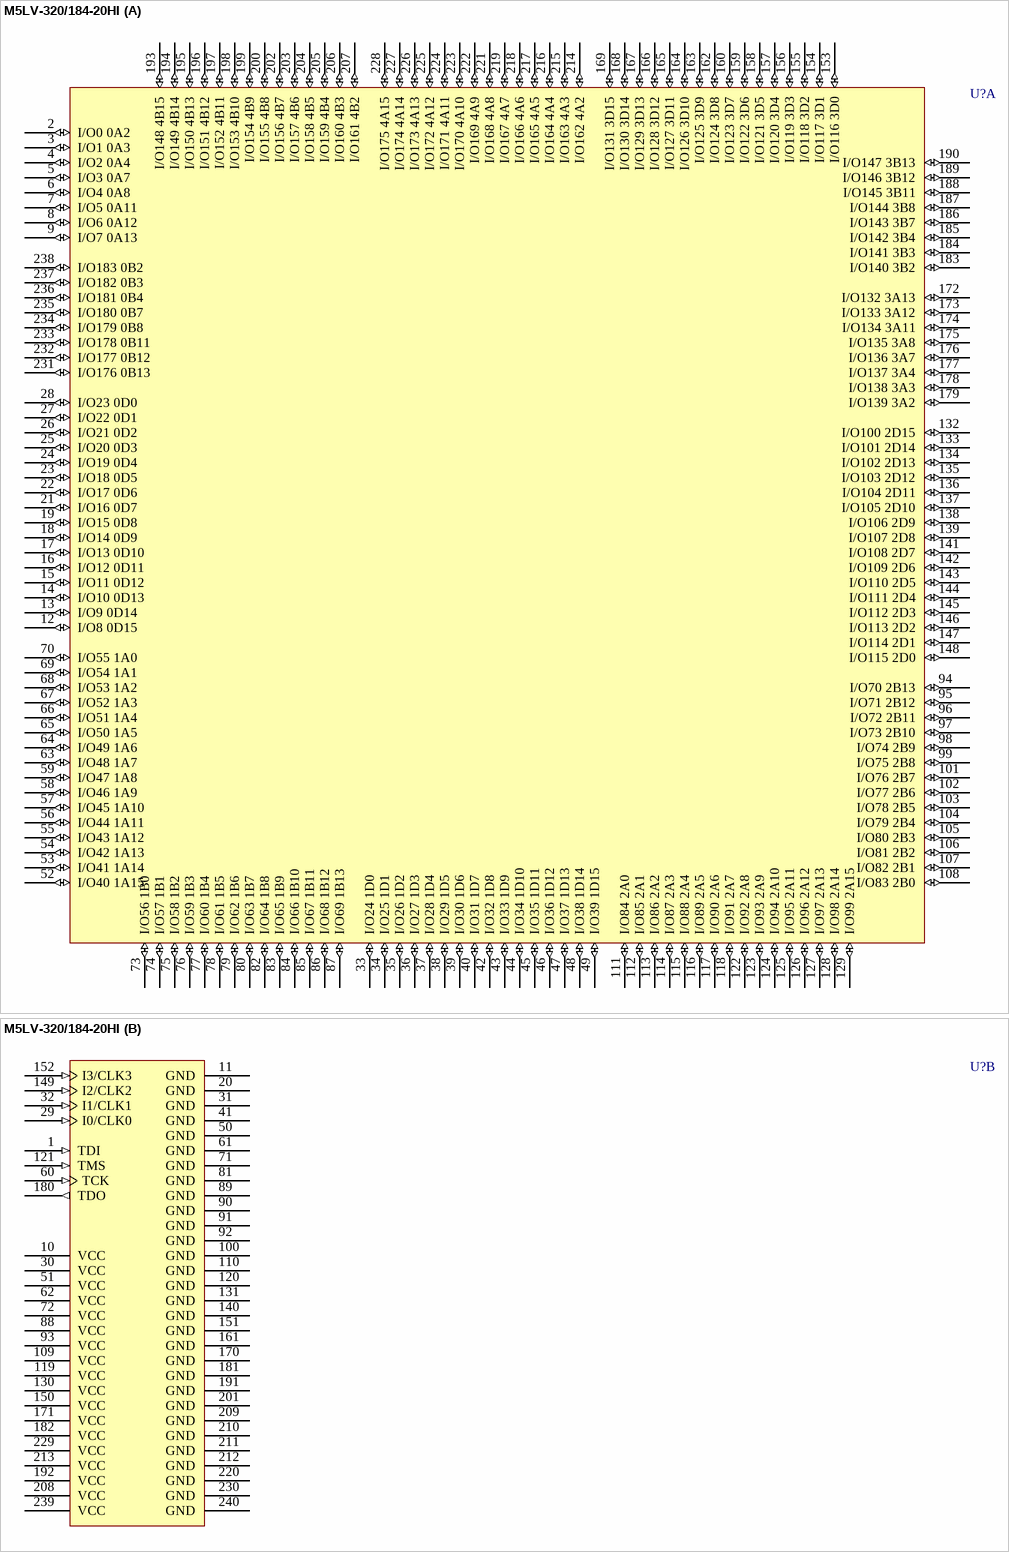
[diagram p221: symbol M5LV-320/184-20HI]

## M5LV-320/184-20HI
designator U?
High-Density and High-I/O Complex PLD
footprint PQFP240_N (Shrink QFP, 240-Leads, Body 32x32mm, Pitch 0.5mm, IPC Medium Density)
footprint PQFP240_L (Shrink QFP, 240-Leads, Body 32x32mm, Pitch 0.5mm, IPC High Density)
footprint PQFP240_M (Shrink QFP, 240-Leads, Body 32x32mm, Pitch 0.5mm, IPC Low Density)
3D model M5LV-PQFP240 (240-Pin Shrink Quad Flat Pack 0.5 mm Pitch)
part A pins: 2 I/O0 0A2 (io), 3 I/O1 0A3 (io), 4 I/O2 0A4 (io), 5 I/O3 0A7 (io), 6 I/O4 0A8 (io), 7 I/O5 0A11 (io), 8 I/O6 0A12 (io), 9 I/O7 0A13 (io), 12 I/O8 0D15 (io), 13 I/O9 0D14 (io), 14 I/O10 0D13 (io), 15 I/O11 0D12 (io), 16 I/O12 0D11 (io), 17 I/O13 0D10 (io), 18 I/O14 0D9 (io), 19 I/O15 0D8 (io), 21 I/O16 0D7 (io), 22 I/O17 0D6 (io), 23 I/O18 0D5 (io), 24 I/O19 0D4 (io), 25 I/O20 0D3 (io), 26 I/O21 0D2 (io), 27 I/O22 0D1 (io), 28 I/O23 0D0 (io), 33 I/O24 1D0 (io), 34 I/O25 1D1 (io), 35 I/O26 1D2 (io), 36 I/O27 1D3 (io), 37 I/O28 1D4 (io), 38 I/O29 1D5 (io), 39 I/O30 1D6 (io), 40 I/O31 1D7 (io), 42 I/O32 1D8 (io), 43 I/O33 1D9 (io), 44 I/O34 1D10 (io), 45 I/O35 1D11 (io), 46 I/O36 1D12 (io), 47 I/O37 1D13 (io), 48 I/O38 1D14 (io), 49 I/O39 1D15 (io), 52 I/O40 1A15 (io), 53 I/O41 1A14 (io), 54 I/O42 1A13 (io), 55 I/O43 1A12 (io), 56 I/O44 1A11 (io), 57 I/O45 1A10 (io), 58 I/O46 1A9 (io), 59 I/O47 1A8 (io), 63 I/O48 1A7 (io), 64 I/O49 1A6 (io), 65 I/O50 1A5 (io), 66 I/O51 1A4 (io), 67 I/O52 1A3 (io), 68 I/O53 1A2 (io), 69 I/O54 1A1 (io), 70 I/O55 1A0 (io), 73 I/O56 1B0 (io), 74 I/O57 1B1 (io), 75 I/O58 1B2 (io), 76 I/O59 1B3 (io), 77 I/O60 1B4 (io), 78 I/O61 1B5 (io), 79 I/O62 1B6 (io), 80 I/O63 1B7 (io), 82 I/O64 1B8 (io), 83 I/O65 1B9 (io), 84 I/O66 1B10 (io), 85 I/O67 1B11 (io), 86 I/O68 1B12 (io), 87 I/O69 1B13 (io), 94 I/O70 2B13 (io), 95 I/O71 2B12 (io), 96 I/O72 2B11 (io), 97 I/O73 2B10 (io), 98 I/O74 2B9 (io), 99 I/O75 2B8 (io), 101 I/O76 2B7 (io), 102 I/O77 2B6 (io), 103 I/O78 2B5 (io), 104 I/O79 2B4 (io), 105 I/O80 2B3 (io), 106 I/O81 2B2 (io), 107 I/O82 2B1 (io), 108 I/O83 2B0 (io), 111 I/O84 2A0 (io), 112 I/O85 2A1 (io), 113 I/O86 2A2 (io), 114 I/O87 2A3 (io), 115 I/O88 2A4 (io), 116 I/O89 2A5 (io), 117 I/O90 2A6 (io), 118 I/O91 2A7 (io), 122 I/O92 2A8 (io), 123 I/O93 2A9 (io), 124 I/O94 2A10 (io), 125 I/O95 2A11 (io), 126 I/O96 2A12 (io), 127 I/O97 2A13 (io), 128 I/O98 2A14 (io), 129 I/O99 2A15 (io), 132 I/O100 2D15 (io), 133 I/O101 2D14 (io), 134 I/O102 2D13 (io), 135 I/O103 2D12 (io), 136 I/O104 2D11 (io), 137 I/O105 2D10 (io), 138 I/O106 2D9 (io), 139 I/O107 2D8 (io), 141 I/O108 2D7 (io), 142 I/O109 2D6 (io), 143 I/O110 2D5 (io), 144 I/O111 2D4 (io), 145 I/O112 2D3 (io), 146 I/O113 2D2 (io), 147 I/O114 2D1 (io), 148 I/O115 2D0 (io), 153 I/O116 3D0 (io), 154 I/O117 3D1 (io), 155 I/O118 3D2 (io), 156 I/O119 3D3 (io), 157 I/O120 3D4 (io), 158 I/O121 3D5 (io), 159 I/O122 3D6 (io), 160 I/O123 3D7 (io), 162 I/O124 3D8 (io), 163 I/O125 3D9 (io), 164 I/O126 3D10 (io), 165 I/O127 3D11 (io), 166 I/O128 3D12 (io), 167 I/O129 3D13 (io), 168 I/O130 3D14 (io), 169 I/O131 3D15 (io), 172 I/O132 3A13 (io), 173 I/O133 3A12 (io), 174 I/O134 3A11 (io), 175 I/O135 3A8 (io), 176 I/O136 3A7 (io), 177 I/O137 3A4 (io), 178 I/O138 3A3 (io), 179 I/O139 3A2 (io), 183 I/O140 3B2 (io), 184 I/O141 3B3 (io), 185 I/O142 3B4 (io), 186 I/O143 3B7 (io), 187 I/O144 3B8 (io), 188 I/O145 3B11 (io), 189 I/O146 3B12 (io), 190 I/O147 3B13 (io), 193 I/O148 4B15 (io), 194 I/O149 4B14 (io), 195 I/O150 4B13 (io), 196 I/O151 4B12 (io), 197 I/O152 4B11 (io), 198 I/O153 4B10 (io), 199 I/O154 4B9 (io), 200 I/O155 4B8 (io), 202 I/O156 4B7 (io), 203 I/O157 4B6 (io), 204 I/O158 4B5 (io), 205 I/O159 4B4 (io), 206 I/O160 4B3 (io), 207 I/O161 4B2 (io), 214 I/O162 4A2 (io), 215 I/O163 4A3 (io), 216 I/O164 4A4 (io), 217 I/O165 4A5 (io), 218 I/O166 4A6 (io), 219 I/O167 4A7 (io), 221 I/O168 4A8 (io), 222 I/O169 4A9 (io), 223 I/O170 4A10 (io), 224 I/O171 4A11 (io), 225 I/O172 4A12 (io), 226 I/O173 4A13 (io), 227 I/O174 4A14 (io), 228 I/O175 4A15 (io), 231 I/O176 0B13 (io), 232 I/O177 0B12 (io), 233 I/O178 0B11 (io), 234 I/O179 0B8 (io), 235 I/O180 0B7 (io), 236 I/O181 0B4 (io), 237 I/O182 0B3 (io), 238 I/O183 0B2 (io)
part B pins: 1 TDI (in), 10 VCC (power), 11 GND (power), 20 GND (power), 29 I0/CLK0 (in), 30 VCC (power), 31 GND (power), 32 I1/CLK1 (in), 41 GND (power), 50 GND (power), 51 VCC (power), 60 TCK (in), 61 GND (power), 62 VCC (power), 71 GND (power), 72 VCC (power), 81 GND (power), 88 VCC (power), 89 GND (power), 90 GND (power), 91 GND (power), 92 GND (power), 93 VCC (power), 100 GND (power), 109 VCC (power), 110 GND (power), 119 VCC (power), 120 GND (power), 121 TMS (in), 130 VCC (power), 131 GND (power), 140 GND (power), 149 I2/CLK2 (in), 150 VCC (power), 151 GND (power), 152 I3/CLK3 (in), 161 GND (power), 170 GND (power), 171 VCC (power), 180 TDO (out), 181 GND (power), 182 VCC (power), 191 GND (power), 192 VCC (power), 201 GND (power), 208 VCC (power), 209 GND (power), 210 GND (power), 211 GND (power), 212 GND (power), 213 VCC (power), 220 GND (power), 229 VCC (power), 230 GND (power), 239 VCC (power), 240 GND (power)

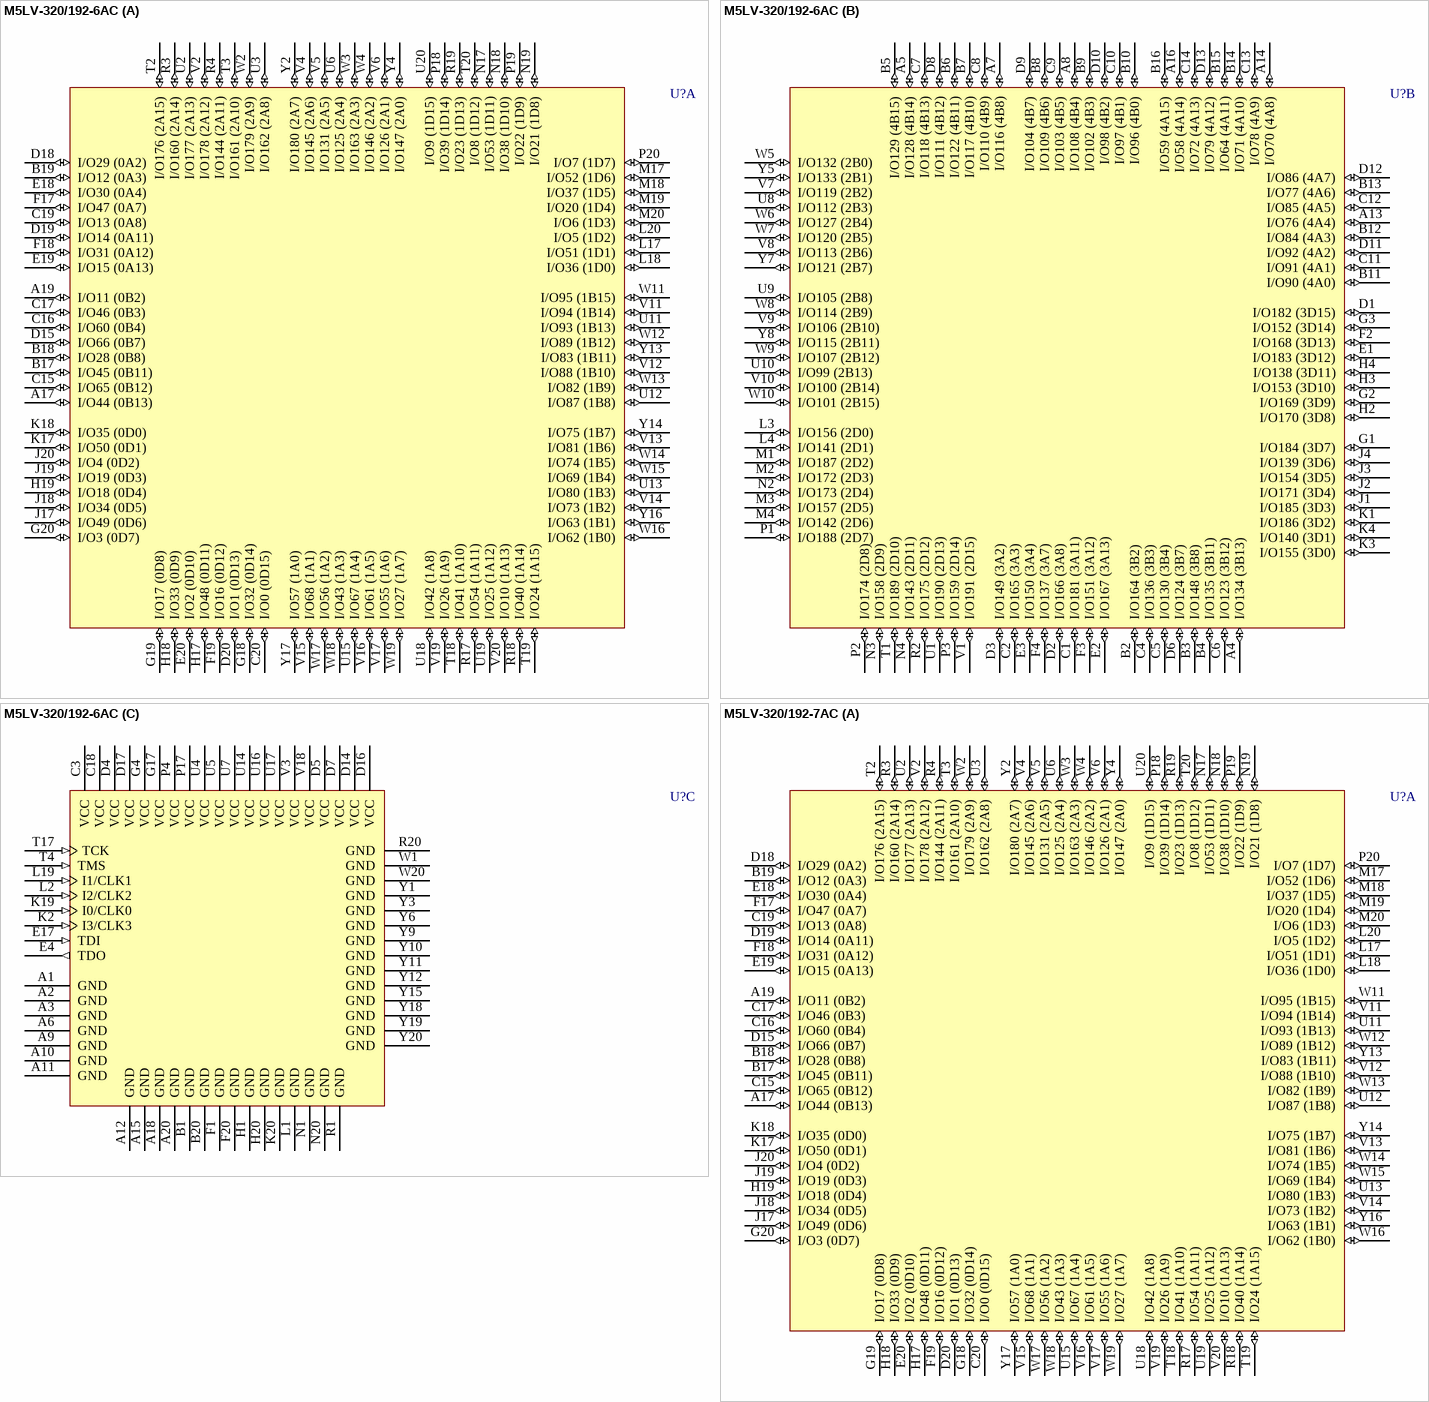
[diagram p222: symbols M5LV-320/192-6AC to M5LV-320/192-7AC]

## M5LV-320/192-6AC
designator U?
High-Density and High-I/O Complex PLD
footprint SBGA256 (BGA, 256-Leads, Body 27x27mm, Pitch 1.27mm)
3D model M5LV-SBGA256 (256-Ball Super Ball Grid Array (SBGA256))
part A pins: A17 I/O44 (0B13) (io), A19 I/O11 (0B2) (io), B17 I/O45 (0B11) (io), B18 I/O28 (0B8) (io), B19 I/O12 (0A3) (io), C15 I/O65 (0B12) (io), C16 I/O60 (0B4) (io), C17 I/O46 (0B3) (io), C19 I/O13 (0A8) (io), C20 I/O0 (0D15) (io), D15 I/O66 (0B7) (io), D18 I/O29 (0A2) (io), D19 I/O14 (0A11) (io), D20 I/O1 (0D13) (io), E18 I/O30 (0A4) (io), E19 I/O15 (0A13) (io), E20 I/O2 (0D10) (io), F17 I/O47 (0A7) (io), F18 I/O31 (0A12) (io), F19 I/O16 (0D12) (io), G18 I/O32 (0D14) (io), G19 I/O17 (0D8) (io), G20 I/O3 (0D7) (io), H17 I/O48 (0D11) (io), H18 I/O33 (0D9) (io), H19 I/O18 (0D4) (io), J17 I/O49 (0D6) (io), J18 I/O34 (0D5) (io), J19 I/O19 (0D3) (io), J20 I/O4 (0D2) (io), K17 I/O50 (0D1) (io), K18 I/O35 (0D0) (io), L17 I/O51 (1D1) (io), L18 I/O36 (1D0) (io), L20 I/O5 (1D2) (io), M17 I/O52 (1D6) (io), M18 I/O37 (1D5) (io), M19 I/O20 (1D4) (io), M20 I/O6 (1D3) (io), N17 I/O53 (1D11) (io), N18 I/O38 (1D10) (io), N19 I/O21 (1D8) (io), P18 I/O39 (1D14) (io), P19 I/O22 (1D9) (io), P20 I/O7 (1D7) (io), R3 I/O160 (2A14) (io), R4 I/O144 (2A11) (io), R17 I/O54 (1A11) (io), R18 I/O40 (1A14) (io), R19 I/O23 (1D13) (io), T2 I/O176 (2A15) (io), T3 I/O161 (2A10) (io), T18 I/O41 (1A10) (io), T19 I/O24 (1A15) (io), T20 I/O8 (1D12) (io), U2 I/O177 (2A13) (io), U3 I/O162 (2A8) (io), U6 I/O125 (2A4) (io), U11 I/O93 (1B13) (io), U12 I/O87 (1B8) (io), U13 I/O80 (1B3) (io), U15 I/O67 (1A4) (io), U18 I/O42 (1A8) (io), U19 I/O25 (1A12) (io), U20 I/O9 (1D15) (io), V2 I/O178 (2A12) (io), V4 I/O145 (2A6) (io), V5 I/O131 (2A5) (io), V6 I/O126 (2A1) (io), V11 I/O94 (1B14) (io), V12 I/O88 (1B10) (io), V13 I/O81 (1B6) (io), V14 I/O73 (1B2) (io), V15 I/O68 (1A1) (io), V16 I/O61 (1A5) (io), V17 I/O55 (1A6) (io), V19 I/O26 (1A9) (io), V20 I/O10 (1A13) (io), W2 I/O179 (2A9) (io), W3 I/O163 (2A3) (io), W4 I/O146 (2A2) (io), W11 I/O95 (1B15) (io), W12 I/O89 (1B12) (io), W13 I/O82 (1B9) (io), W14 I/O74 (1B5) (io), W15 I/O69 (1B4) (io), W16 I/O62 (1B0) (io), W17 I/O56 (1A2) (io), W18 I/O43 (1A3) (io), W19 I/O27 (1A7) (io), Y2 I/O180 (2A7) (io), Y4 I/O147 (2A0) (io), Y13 I/O83 (1B11) (io), Y14 I/O75 (1B7) (io), Y16 I/O63 (1B1) (io), Y17 I/O57 (1A0) (io)
part B pins: A4 I/O134 (3B13) (io), A5 I/O128 (4B14) (io), A7 I/O116 (4B8) (io), A8 I/O108 (4B4) (io), A13 I/O76 (4A4) (io), A14 I/O70 (4A8) (io), A16 I/O58 (4A14) (io), B2 I/O164 (3B2) (io), B3 I/O148 (3B8) (io), B4 I/O135 (3B11) (io), B5 I/O129 (4B15) (io), B6 I/O122 (4B11) (io), B7 I/O117 (4B10) (io), B8 I/O109 (4B6) (io), B9 I/O102 (4B3) (io), B10 I/O96 (4B0) (io), B11 I/O90 (4A0) (io), B12 I/O84 (4A3) (io), B13 I/O77 (4A6) (io), B14 I/O71 (4A10) (io), B15 I/O64 (4A11) (io), B16 I/O59 (4A15) (io), C1 I/O181 (3A11) (io), C2 I/O165 (3A3) (io), C4 I/O136 (3B3) (io), C5 I/O130 (3B4) (io), C6 I/O123 (3B12) (io), C7 I/O118 (4B13) (io), C8 I/O110 (4B9) (io), C9 I/O103 (4B5) (io), C10 I/O97 (4B1) (io), C11 I/O91 (4A1) (io), C12 I/O85 (4A5) (io), C13 I/O78 (4A9) (io), C14 I/O72 (4A13) (io), D1 I/O182 (3D15) (io), D2 I/O166 (3A8) (io), D3 I/O149 (3A2) (io), D6 I/O124 (3B7) (io), D8 I/O111 (4B12) (io), D9 I/O104 (4B7) (io), D10 I/O98 (4B2) (io), D11 I/O92 (4A2) (io), D12 I/O86 (4A7) (io), D13 I/O79 (4A12) (io), E1 I/O183 (3D12) (io), E2 I/O167 (3A13) (io), E3 I/O150 (3A4) (io), F2 I/O168 (3D13) (io), F3 I/O151 (3A12) (io), F4 I/O137 (3A7) (io), G1 I/O184 (3D7) (io), G2 I/O169 (3D9) (io), G3 I/O152 (3D14) (io), H2 I/O170 (3D8) (io), H3 I/O153 (3D10) (io), H4 I/O138 (3D11) (io), J1 I/O185 (3D3) (io), J2 I/O171 (3D4) (io), J3 I/O154 (3D5) (io), J4 I/O139 (3D6) (io), K1 I/O186 (3D2) (io), K3 I/O155 (3D0) (io), K4 I/O140 (3D1) (io), L3 I/O156 (2D0) (io), L4 I/O141 (2D1) (io), M1 I/O187 (2D2) (io), M2 I/O172 (2D3) (io), M3 I/O157 (2D5) (io), M4 I/O142 (2D6) (io), N2 I/O173 (2D4) (io), N3 I/O158 (2D9) (io), N4 I/O143 (2D11) (io), P1 I/O188 (2D7) (io), P2 I/O174 (2D8) (io), P3 I/O159 (2D14) (io), R2 I/O175 (2D12) (io), T1 I/O189 (2D10) (io), U1 I/O190 (2D13) (io), U8 I/O112 (2B3) (io), U9 I/O105 (2B8) (io), U10 I/O99 (2B13) (io), V1 I/O191 (2D15) (io), V7 I/O119 (2B2) (io), V8 I/O113 (2B6) (io), V9 I/O106 (2B10) (io), V10 I/O100 (2B14) (io), W5 I/O132 (2B0) (io), W6 I/O127 (2B4) (io), W7 I/O120 (2B5) (io), W8 I/O114 (2B9) (io), W9 I/O107 (2B12) (io), W10 I/O101 (2B15) (io), Y5 I/O133 (2B1) (io), Y7 I/O121 (2B7) (io), Y8 I/O115 (2B11) (io)
part C pins: A1 GND (power), A2 GND (power), A3 GND (power), A6 GND (power), A9 GND (power), A10 GND (power), A11 GND (power), A12 GND (power), A15 GND (power), A18 GND (power), A20 GND (power), B1 GND (power), B20 GND (power), C3 VCC (power), C18 VCC (power), D4 VCC (power), D5 VCC (power), D7 VCC (power), D14 VCC (power), D16 VCC (power), D17 VCC (power), E4 TDO (out), E17 TDI (in), F1 GND (power), F20 GND (power), G4 VCC (power), G17 VCC (power), H1 GND (power), H20 GND (power), K2 I3/CLK3 (in), K19 I0/CLK0 (in), K20 GND (power), L1 GND (power), L2 I2/CLK2 (in), L19 I1/CLK1 (in), N1 GND (power), N20 GND (power), P4 VCC (power), P17 VCC (power), R1 GND (power), R20 GND (power), T4 TMS (in), T17 TCK (in), U4 VCC (power), U5 VCC (power), U7 VCC (power), U14 VCC (power), U16 VCC (power), U17 VCC (power), V3 VCC (power), V18 VCC (power), W1 GND (power), W20 GND (power), Y1 GND (power), Y3 GND (power), Y6 GND (power), Y9 GND (power), Y10 GND (power), Y11 GND (power), Y12 GND (power), Y15 GND (power), Y18 GND (power), Y19 GND (power), Y20 GND (power)

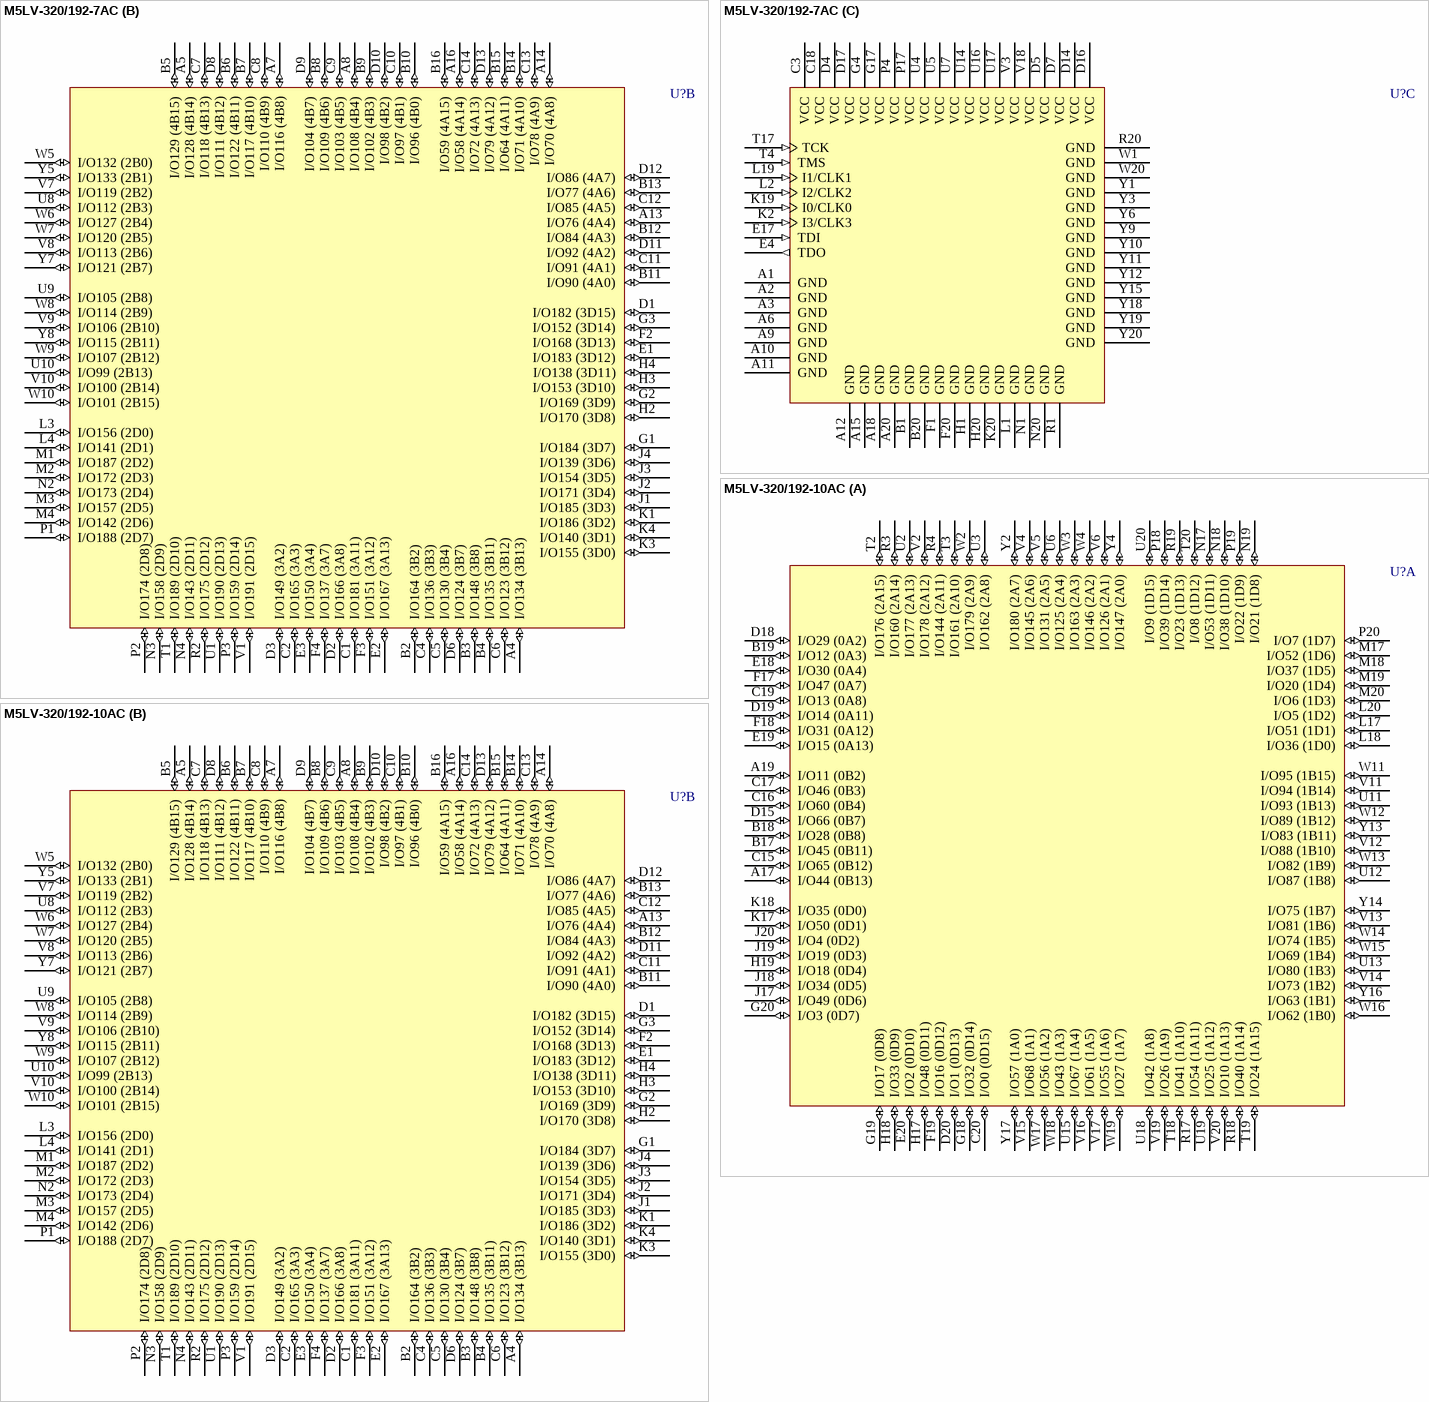
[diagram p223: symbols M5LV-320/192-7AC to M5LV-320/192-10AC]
